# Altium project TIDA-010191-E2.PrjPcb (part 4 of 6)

## Sheet TIDA-010191-E2_LMX2615_LO.SchDoc: LMK0482x
size 558 x 431 mm; Date: Not shown in title block; ApprovedBy: Not shown in title block; CheckedBy: Not shown in title block; Author: Not shown in title block; CompanyName: Not shown in title block; DrawnBy: Avinash N; Engineer: Not shown in title block; Organization: Not shown in title block; Address1: Not shown in title block; Address2: Not shown in title block; Address3: Not shown in title block; Address4: Not shown in title block; DocumentNumber: 5; Revision: Use project parameter SCH_Rev; SheetNumber: 5; SheetTotal: 9; PageSetup: Record=PageOptions¦CenterHorizontal=True¦CenterVertical=True¦PrintScale=1.00¦XCorrection=1.00¦YCorrection=1.00¦PrintKind=0¦BorderSize=5000000¦LeftOffset=0¦BottomOffset=0¦Orientation=2¦PaperLength=1000¦PaperWidth=1000¦Scale=100¦PaperSource=15¦PrintQuality=600¦MediaType=1¦DitherType=10¦PaperKind=Letter¦PrintScaleMode=1
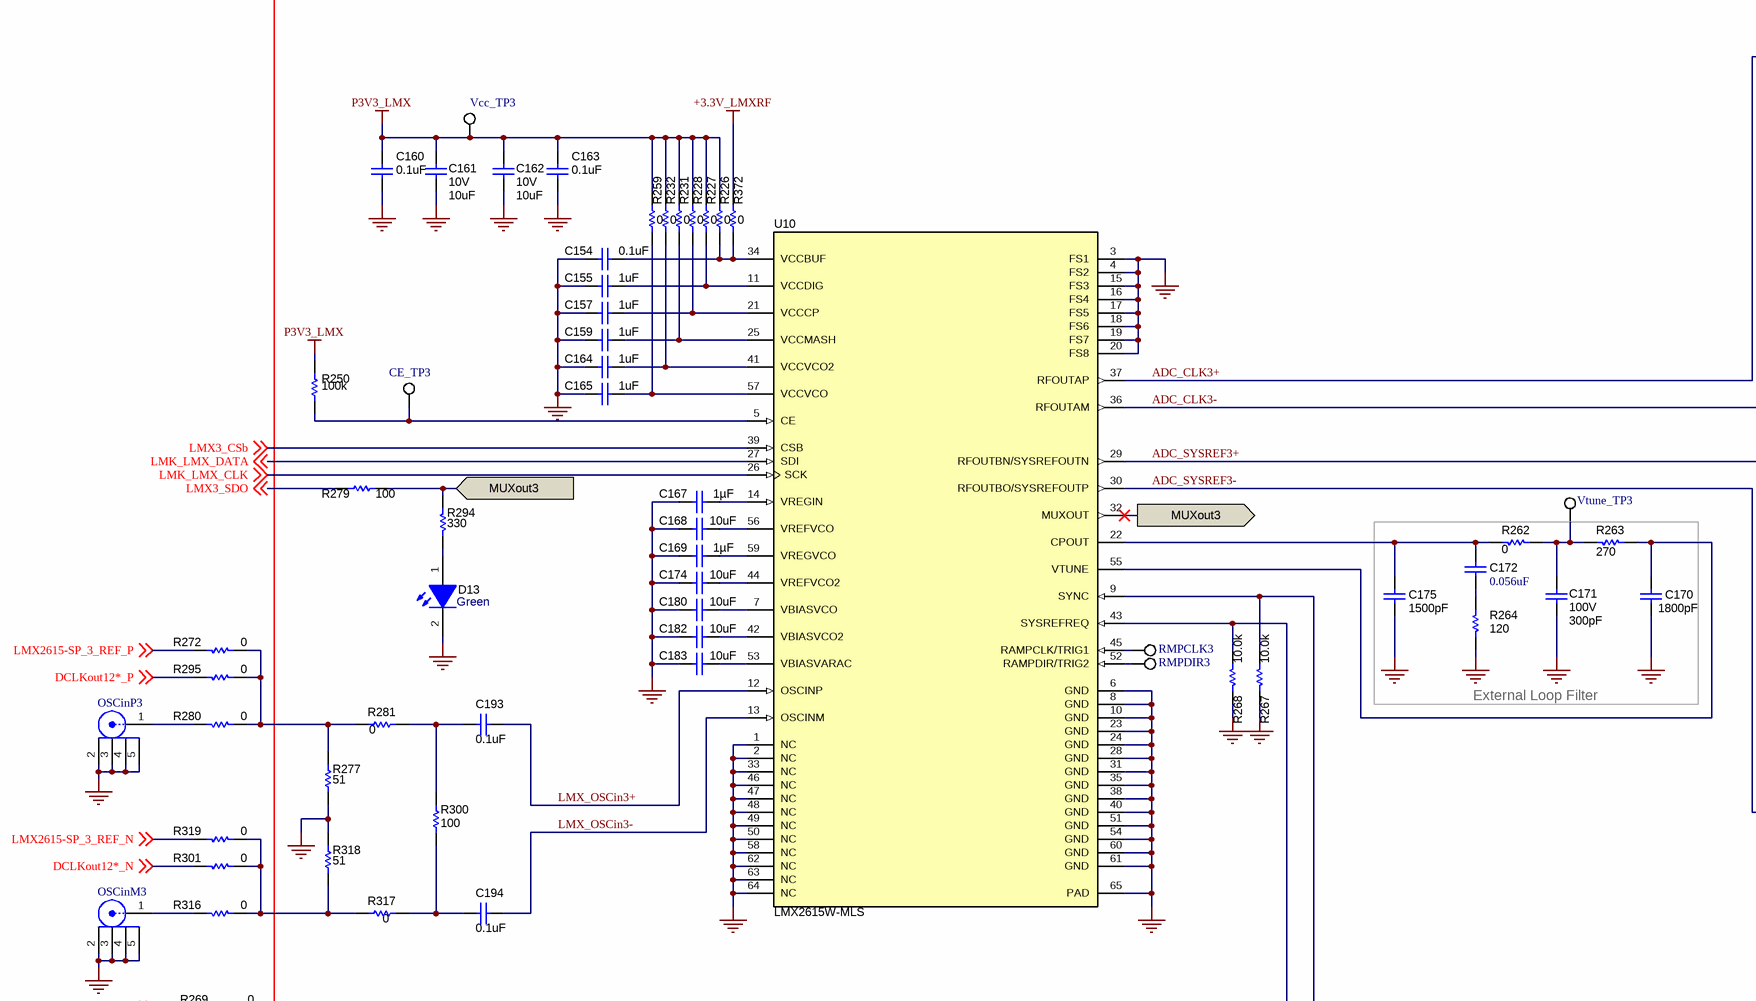
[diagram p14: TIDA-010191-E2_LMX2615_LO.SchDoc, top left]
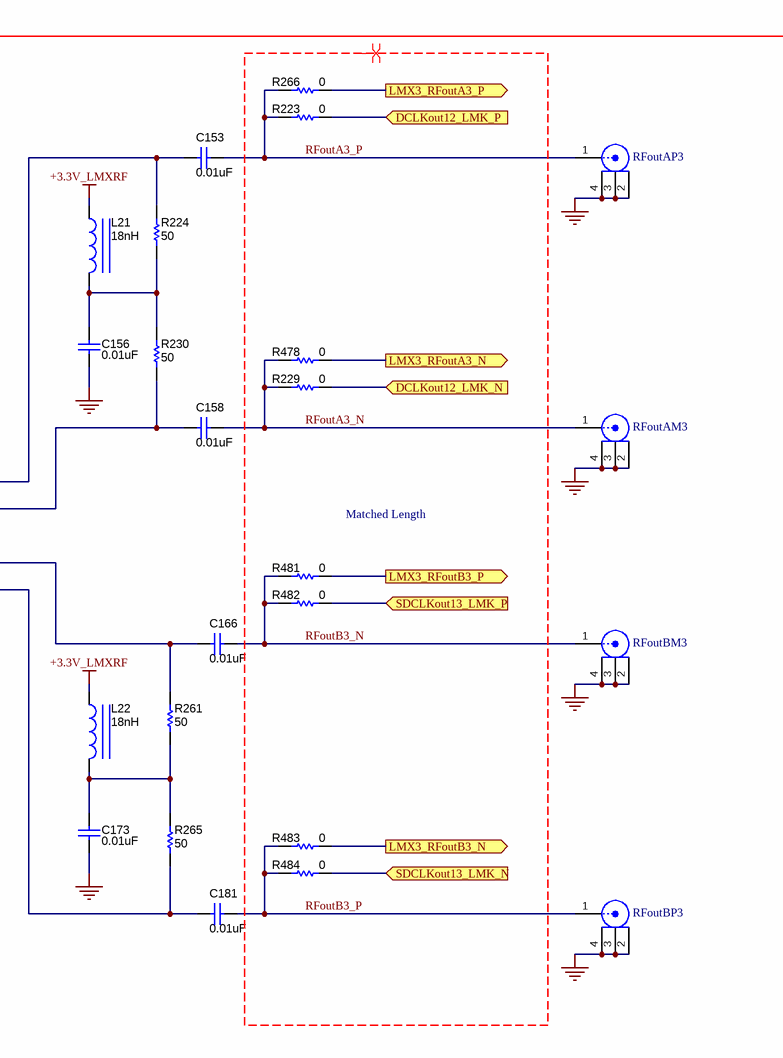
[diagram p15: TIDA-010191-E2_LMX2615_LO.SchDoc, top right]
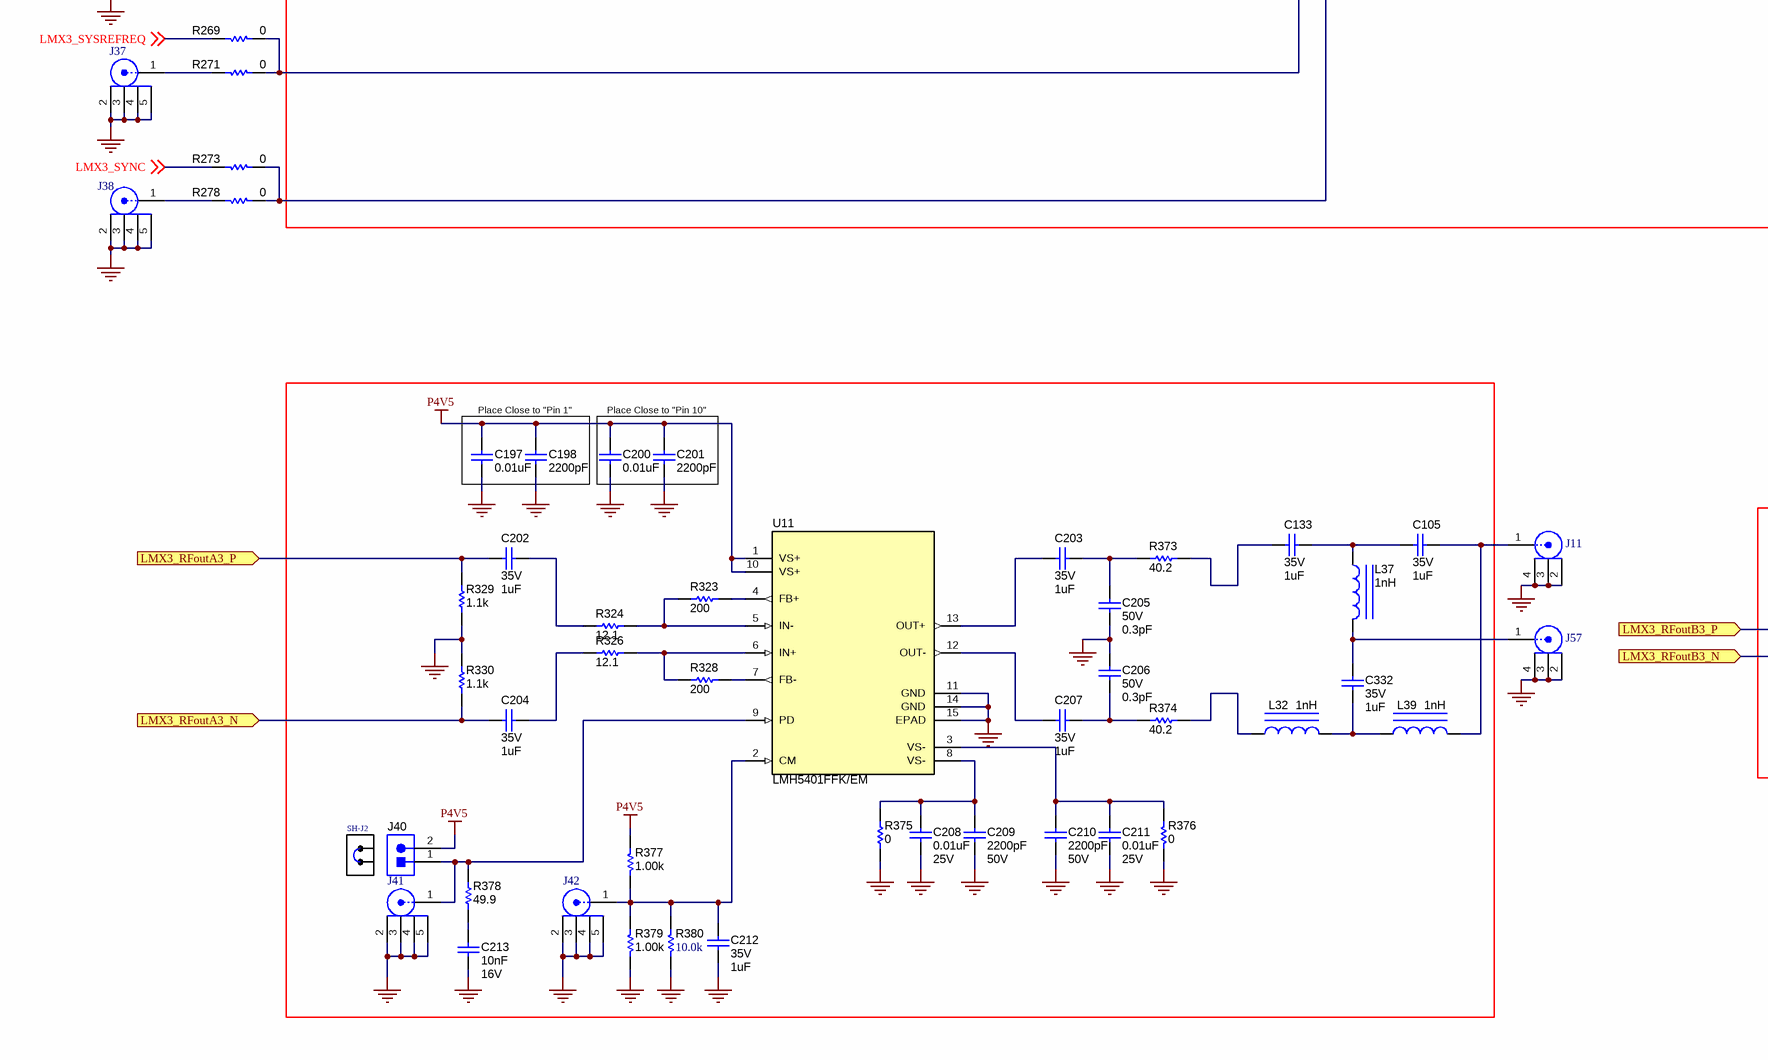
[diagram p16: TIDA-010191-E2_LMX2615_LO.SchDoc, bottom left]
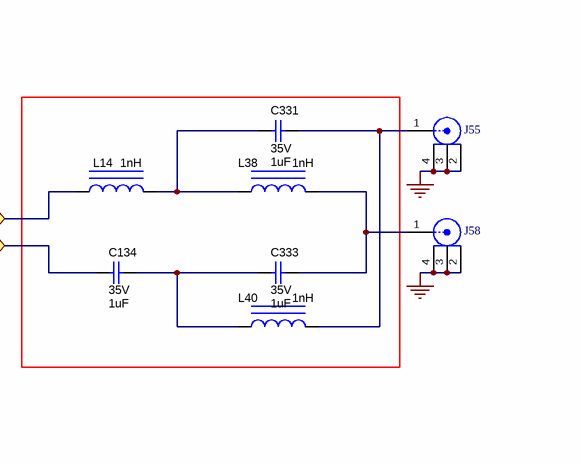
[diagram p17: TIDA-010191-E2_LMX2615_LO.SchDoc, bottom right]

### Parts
C105  VDC_V: 35V  ValueDisplayed: 1uF  [0402]  (hidden comment: GRM155R6YA105KE11D)
C133  VDC_V: 35V  ValueDisplayed: 1uF  [0402]  (hidden comment: GRM155R6YA105KE11D)
C134  VDC_V: 35V  ValueDisplayed: 1uF  [0402]  (hidden comment: GRM155R6YA105KE11D)
C153  ValueDisplayed: 0.01uF  [0402_065]  (hidden comment: Capacitor)
C154  ValueDisplayed: 0.1uF  [0603L]  (hidden comment: Capacitor)
C155  ValueDisplayed: 1uF  [0603]  (hidden comment: Capacitor)
C156  ValueDisplayed: 0.01uF  [0402_065]  (hidden comment: Capacitor)
C157  ValueDisplayed: 1uF  [0603L]  (hidden comment: Capacitor)
C158  ValueDisplayed: 0.01uF  [0402_065]  (hidden comment: Capacitor)
C159  ValueDisplayed: 1uF  [0603L]  (hidden comment: Capacitor)
C160  ValueDisplayed: 0.1uF  [0603]  (hidden comment: Capacitor)
C161  VDC_V: 10V  ValueDisplayed: 10uF  [0805_HV]  (hidden comment: CMP-0007732-2)
C162  VDC_V: 10V  ValueDisplayed: 10uF  [0805_HV]  (hidden comment: CMP-0007732-2)
C163  ValueDisplayed: 0.1uF  [0603]  (hidden comment: Capacitor)
C164  ValueDisplayed: 1uF  [0603]  (hidden comment: Capacitor)
C165  ValueDisplayed: 1uF  [0603]  (hidden comment: Capacitor)
C166  ValueDisplayed: 0.01uF  [0402_065]  (hidden comment: Capacitor)
C167  Cap_F: 1µF  [0603]  (hidden comment: CMP-0007037-4)
C168  ValueDisplayed: 10uF  [0603]  (hidden comment: CMP-0007003-5)
C169  Cap_F: 1µF  [0603]  (hidden comment: CMP-0007037-4)
C170  ValueDisplayed: 1800pF  [0603]  (hidden comment: Capacitor)
C171  VDC_V: 100V  ValueDisplayed: 300pF  [0603]  (hidden comment: CMP-0007262-4)
C172  ValueDisplayed: 0.056uF  [0603]  (hidden comment: Capacitor)
C173  ValueDisplayed: 0.01uF  [0402_065]  (hidden comment: Capacitor)
C174  ValueDisplayed: 10uF  [0603]  (hidden comment: CMP-0007003-5)
C175  ValueDisplayed: 1500pF  [0603]  (hidden comment: Capacitor)
C180  ValueDisplayed: 10uF  [0603]  (hidden comment: CMP-0007003-5)
C181  ValueDisplayed: 0.01uF  [0402_065]  (hidden comment: Capacitor)
C182  ValueDisplayed: 10uF  [0603]  (hidden comment: CMP-0007003-5)
C183  ValueDisplayed: 10uF  [0603]  (hidden comment: CMP-0007003-5)
C193  ValueDisplayed: 0.1uF  [0603L]  (hidden comment: Capacitor)
C194  ValueDisplayed: 0.1uF  [0603L]  (hidden comment: Capacitor)
C197  ValueDisplayed: 0.01uF  [0306]  (hidden comment: Capacitor)
C198  ValueDisplayed: 2200pF  [0306]  (hidden comment: Capacitor)
C200  ValueDisplayed: 0.01uF  [0306]  (hidden comment: Capacitor)
C201  ValueDisplayed: 2200pF  [0306]  (hidden comment: Capacitor)
C202  VDC_V: 35V  ValueDisplayed: 1uF  [0402]  (hidden comment: GRM155R6YA105KE11D)
C203  VDC_V: 35V  ValueDisplayed: 1uF  [0402]  (hidden comment: GRM155R6YA105KE11D)
C204  VDC_V: 35V  ValueDisplayed: 1uF  [0402]  (hidden comment: GRM155R6YA105KE11D)
C205  VDC_V: 50V  ValueDisplayed: 0.3pF  [0402]  (hidden comment: 500R07S0R3BV4T)
C206  VDC_V: 50V  ValueDisplayed: 0.3pF  [0402]  (hidden comment: 500R07S0R3BV4T)
C207  VDC_V: 35V  ValueDisplayed: 1uF  [0402]  (hidden comment: GRM155R6YA105KE11D)
C208  ValueDisplayed: 0.01uF  VDC_V: 25V  [0306]  (hidden comment: CMP-0009490-2)
C209  ValueDisplayed: 2200pF  VDC_V: 50V  [0306]  (hidden comment: CMP-0009493-2)
C210  ValueDisplayed: 2200pF  VDC_V: 50V  [0306]  (hidden comment: CMP-0009493-2)
C211  ValueDisplayed: 0.01uF  VDC_V: 25V  [0306]  (hidden comment: CMP-0009490-2)
C212  VDC_V: 35V  ValueDisplayed: 1uF  [0402]  (hidden comment: GRM155R6YA105KE11D)
C213  Cap_F: 10nF  VDC_V: 16V  [0603]  (hidden comment: GRM188R71C103KA01D)
C331  VDC_V: 35V  ValueDisplayed: 1uF  [0402]  (hidden comment: GRM155R6YA105KE11D)
C332  VDC_V: 35V  ValueDisplayed: 1uF  [0402]  (hidden comment: GRM155R6YA105KE11D)
C333  VDC_V: 35V  ValueDisplayed: 1uF  [0402]  (hidden comment: GRM155R6YA105KE11D)
CE_TP3  5007  [Keystone5007]  (value not drawn)
D13  value Green  [LTST-C191_Green]  (hidden comment: CMP-0002891-3)
J11  142-0771-831  [Johnson_142-0771-831]  (value not drawn)
J37  142-0701-201  [Johnson_142-0701-20x]  (value not drawn)
J38  142-0701-201  [Johnson_142-0701-20x]  (value not drawn)
J40  HTSW-102-07-G-S  [Samtec_HTSW-102-07-G-S]  (value not drawn)
J41  SMA_Contact1_GND2345  [Johnson_142-0701-20x]  (value not drawn)
J42  SMA_Contact1_GND2345  [Johnson_142-0701-20x]  (value not drawn)
J55  142-0771-831  [Johnson_142-0771-831]  (value not drawn)
J57  142-0771-831  [Johnson_142-0771-831]  (value not drawn)
J58  142-0771-831  [Johnson_142-0771-831]  (value not drawn)
L14  ValueDisplayed: 1nH  [IND_LQG15H]  (hidden comment: Inductor_Iron)
L21  ValueDisplayed: 18nH  [IND_LQG15H]  (hidden comment: CMP-0058614-1)
L22  ValueDisplayed: 18nH  [IND_LQG15H]  (hidden comment: CMP-0058614-1)
L32  ValueDisplayed: 1nH  [IND_LQG15H]  (hidden comment: Inductor_Iron)
L37  ValueDisplayed: 1nH  [IND_LQG15H]  (hidden comment: Inductor_Iron)
L38  ValueDisplayed: 1nH  [IND_LQG15H]  (hidden comment: Inductor_Iron)
L39  ValueDisplayed: 1nH  [IND_LQG15H]  (hidden comment: Inductor_Iron)
L40  ValueDisplayed: 1nH  [IND_LQG15H]  (hidden comment: Inductor_Iron)
OSCinM3  CMP-0055819-1  [Johnson_142-0701-20x]  (value not drawn)
OSCinP3  CMP-0055819-1  [Johnson_142-0701-20x]  (value not drawn)
R223  ValueDisplayed: 0  [0402]  (hidden comment: Resistor)
R224  ValueDisplayed: 50  [0402]  (hidden comment: CMP-0026791-1)
R226  value 0  [0603]  (hidden comment: Resistor)
R227  value 0  [0603]  (hidden comment: Resistor)
R228  value 0  [0603L]  (hidden comment: Resistor)
R229  ValueDisplayed: 0  [0402]  (hidden comment: Resistor)
R230  ValueDisplayed: 50  [0402]  (hidden comment: CMP-0026791-1)
R231  value 0  [0603L]  (hidden comment: Resistor)
R232  value 0  [0603]  (hidden comment: Resistor)
R250  ValueDisplayed: 100k  [0603]  (hidden comment: Resistor)
R259  value 0  [0603]  (hidden comment: Resistor)
R261  ValueDisplayed: 50  [0402]  (hidden comment: CMP-0026791-1)
R262  ValueDisplayed: 0  [0603]  (hidden comment: Resistor)
R263  ValueDisplayed: 270  [0603]  (hidden comment: Resistor)
R264  ValueDisplayed: 120  [0603]  (hidden comment: Resistor)
R265  ValueDisplayed: 50  [0402]  (hidden comment: CMP-0026791-1)
R266  ValueDisplayed: 0  [0402]  (hidden comment: Resistor)
R267  ValueDisplayed: 10.0k  [0402]  (hidden comment: Resistor)
R268  ValueDisplayed: 10.0k  [0402]  (hidden comment: Resistor)
R269  ValueDisplayed: 0  [0402]  (hidden comment: CMP-0026822-3)
R271  ValueDisplayed: 0  [0402]  (hidden comment: CMP-0026822-3)
R272  ValueDisplayed: 0  [0402]  (hidden comment: CMP-0026822-3)
R273  ValueDisplayed: 0  [0402]  (hidden comment: CMP-0026822-3)
R277  ValueDisplayed: 51  [0603]  (hidden comment: Resistor)
R278  ValueDisplayed: 0  [0402]  (hidden comment: Resistor)
R279  ValueDisplayed: 100  [0603]  (hidden comment: CMP-0021991-4)
R280  ValueDisplayed: 0  [0402]  (hidden comment: CMP-0026822-3)
R281  ValueDisplayed: 0  [0603]  (hidden comment: Resistor)
R294  value 330  [0603]  (hidden comment: Resistor)
R295  ValueDisplayed: 0  [0402]  (hidden comment: CMP-0026822-3)
R300  ValueDisplayed: 100  [0603]  (hidden comment: CMP-0021991-4)
R301  ValueDisplayed: 0  [0402]  (hidden comment: CMP-0026822-3)
R316  ValueDisplayed: 0  [0402]  (hidden comment: CMP-0026822-3)
R317  ValueDisplayed: 0  [0603]  (hidden comment: Resistor)
R318  ValueDisplayed: 51  [0603]  (hidden comment: Resistor)
R319  ValueDisplayed: 0  [0402]  (hidden comment: CMP-0026822-3)
R323  ValueDisplayed: 200  [0402]  (hidden comment: CRCW0402200RFKED)
R324  ValueDisplayed: 12.1  [0402]  (hidden comment: CRCW040212R1FKED)
R326  ValueDisplayed: 12.1  [0402]  (hidden comment: CRCW040212R1FKED)
R328  ValueDisplayed: 200  [0402]  (hidden comment: CRCW0402200RFKED)
R329  ValueDisplayed: 1.1k  [0402]  (hidden comment: CRCW04021K10JNED)
R330  ValueDisplayed: 1.1k  [0402]  (hidden comment: CRCW04021K10JNED)
R372  value 0  [0603]  (hidden comment: Resistor)
R373  ValueDisplayed: 40.2  [0402]  (hidden comment: CRCW040240R2FKED)
R374  ValueDisplayed: 40.2  [0402]  (hidden comment: CRCW040240R2FKED)
R375  ValueDisplayed: 0  [0402]  (hidden comment: CRCW04020000Z0ED)
R376  ValueDisplayed: 0  [0402]  (hidden comment: CRCW04020000Z0ED)
R377  ValueDisplayed: 1.00k  [0603]  (hidden comment: CRCW06031K00FKEA)
R378  ValueDisplayed: 49.9  [0603]  (hidden comment: CRCW060349R9FKEA)
R379  ValueDisplayed: 1.00k  [0603]  (hidden comment: CRCW06031K00FKEA)
R380  ValueDisplayed: 10.0k  [0402]  (hidden comment: ERJ-2RKF1002X)
R478  ValueDisplayed: 0  [0402]  (hidden comment: Resistor)
R481  ValueDisplayed: 0  [0402]  (hidden comment: Resistor)
R482  ValueDisplayed: 0  [0402]  (hidden comment: Resistor)
R483  ValueDisplayed: 0  [0402]  (hidden comment: Resistor)
R484  ValueDisplayed: 0  [0402]  (hidden comment: Resistor)
RFoutAM3  142-0771-831  [Johnson_142-0771-831]  (value not drawn)
RFoutAP3  142-0771-831  [Johnson_142-0771-831]  (value not drawn)
RFoutBM3  142-0771-831  [Johnson_142-0771-831]  (value not drawn)
RFoutBP3  142-0771-831  [Johnson_142-0771-831]  (value not drawn)
RMPCLK3  5007  [Keystone5007]  (value not drawn)
RMPDIR3  5007  [Keystone5007]  (value not drawn)
SH-J2  SPC02SYAN  [SPC02SYAN]  (value not drawn)
U10  LMX2615W-MLS  [HBD0064A_Custom_A]
U11  LMH5401FFK/EM  [FFK0014A]
Vcc_TP3  5007  [Keystone5007]  (value not drawn)
Vtune_TP3  5007  [Keystone5007]  (value not drawn)

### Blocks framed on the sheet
Matched Length: C153-C175 C180-C183 C193 C194 CE_TP3 D13 L21 L22 R223 R224 R226-R232 R250 R259 R261-R268 R277 R279 R281 R294 R300 R317 R318 R372 R478 R481-R484 RFoutAM3 RFoutAP3 RFoutBM3 RFoutBP3 RMPCLK3 RMPDIR3 U10 Vcc_TP3 Vtune_TP3
Place Close to "Pin 1": C197 C198
Place Close to "Pin 10": C200 C201

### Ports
DCLKout12_LMK_N (in), DCLKout12_LMK_P (in), LMX3_RFoutA3_N (in), LMX3_RFoutA3_N (out), LMX3_RFoutA3_P (in), LMX3_RFoutA3_P (out), LMX3_RFoutB3_N (in), LMX3_RFoutB3_N (out), LMX3_RFoutB3_P (in), LMX3_RFoutB3_P (out), MUXout3 (in), MUXout3 (out), SDCLKout13_LMK_N (in), SDCLKout13_LMK_P (in)

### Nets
+3.3V_LMXRF: L21.1 L22.1 R372.1
GND: C154.1 C155.1 C156.1 C157.1 C159.2 C160.1 C161.1 C162.1 C163.1 C164.1 C165.1 C167.1 C168.2 C169.1 C170.1 C171.2 C173.1 C174.2 C175.2 C180.2 C182.2 C183.2 C197.2 C198.2 C200.1 C201.2 C205.2 C206.2 C208.1 C209.2 C210.2 C211.1 C212.2 C213.2 D13.2(K) J11.2 J11.3 J11.4 J37.2 J37.3 J37.4 J37.5 J38.2 J38.3 J38.4 J38.5 J41.2 J41.3 J41.4 J41.5 J42.2 J42.3 J42.4 J42.5 J55.2 J55.3 J55.4 J57.2 J57.3 J57.4 J58.2 J58.3 J58.4 OSCinM3.2 OSCinM3.3 OSCinM3.4 OSCinM3.5 OSCinP3.2 OSCinP3.3 OSCinP3.4 OSCinP3.5 R264.2 R267.2 R268.2 R277.2 R318.1 R329.1 R330.1 R375.1 R376.1 R379.1 R380.1 RFoutAM3.2 RFoutAM3.3 RFoutAM3.4 RFoutAP3.2 RFoutAP3.3 RFoutAP3.4 RFoutBM3.2 RFoutBM3.3 RFoutBM3.4 RFoutBP3.2 RFoutBP3.3 RFoutBP3.4 U10.1(NC) U10.2(NC) U10.3(FS1) U10.4(FS2) U10.6(GND) U10.8(GND) U10.10(GND) U10.15(FS3) U10.16(FS4) U10.17(FS5) U10.18(FS6) U10.19(FS7) U10.20(FS8) U10.23(GND) U10.24(GND) U10.28(GND) U10.31(GND) U10.33(NC) U10.35(GND) U10.38(GND) U10.40(GND) U10.46(NC) U10.47(NC) U10.48(NC) U10.49(NC) U10.50(NC) U10.51(GND) U10.54(GND) U10.58(NC) U10.60(GND) U10.61(GND) U10.62(NC) U10.63(NC) U10.64(NC) U10.65(PAD) U11.11(GND) U11.14(GND) U11.15(EPAD)
P3V3_LMX: C160.2 C161.2 C162.2 C163.2 R226.1 R227.1 R228.1 R231.1 R232.2 R250.1 R259.2 Vcc_TP3.1
P4V5: C197.1 C198.1 C200.2 C201.1 J40.2 R377.1 U11.1(VS+) U11.10(VS+)
ADC_CLK3+: C153.2 R224.1 U10.37(RFOUTAP)
ADC_CLK3-: C158.2 R230.2 U10.36(RFOUTAM)
ADC_SYSREF3+: C166.2 R261.1 U10.29(RFOUTBN/SYSREFOUTN)
ADC_SYSREF3-: C181.2 R265.2 U10.30(RFOUTBO/SYSREFOUTP)
DCLKout12*_N: R301.2 ; off-sheet DCLKout12*_N
DCLKout12*_P: R295.2 ; off-sheet DCLKout12*_P
DCLKout12_LMK_N: R229.2 ; port DCLKout12_LMK_N
DCLKout12_LMK_P: R223.2 ; port DCLKout12_LMK_P
LMK_LMX_CLK: U10.26(SCK) ; off-sheet LMK_LMX_CLK
LMK_LMX_DATA: U10.27(SDI) ; off-sheet LMK_LMX_DATA
LMX3_CSb: U10.39(CSB) ; off-sheet LMX3_CSb
LMX3_RFoutA3_N: C204.2 R330.2 R478.2 ; port LMX3_RFoutA3_N
LMX3_RFoutA3_P: C202.2 R266.2 R329.2 ; port LMX3_RFoutA3_P
LMX3_RFoutB3_N: C134.2 R483.2 ; port LMX3_RFoutB3_N
LMX3_RFoutB3_P: L14.1 R481.2 ; port LMX3_RFoutB3_P
LMX3_SDO: R279.2 ; off-sheet LMX3_SDO
LMX3_SYNC: R273.2 ; off-sheet LMX3_SYNC
LMX3_SYSREFREQ: R269.2 ; off-sheet LMX3_SYSREFREQ
LMX2615-SP_3_REF_N: R319.2 ; off-sheet LMX2615-SP_3_REF_N
LMX2615-SP_3_REF_P: R272.2 ; off-sheet LMX2615-SP_3_REF_P
LMX_OSCin3+: C193.2 U10.12(OSCINP)
LMX_OSCin3-: C194.2 U10.13(OSCINM)
MUXout3: R279.1 R294.2 U10.32(MUXOUT) ; port MUXout3
RFoutA3_N: C158.1 R229.1 R478.1 RFoutAM3.1
RFoutA3_P: C153.1 R223.1 R266.1 RFoutAP3.1
RFoutB3_N: C166.1 R481.1 R482.1 RFoutBM3.1
RFoutB3_P: C181.1 R483.1 R484.1 RFoutBP3.1
SDCLKout13_LMK_N: R484.2 ; port SDCLKout13_LMK_N
SDCLKout13_LMK_P: R482.2 ; port SDCLKout13_LMK_P
NetC105_1: C105.1 J11.1 L39.2
NetC105_2: C105.2 C133.1 L37.1
NetC133_2: C133.2 R373.2
NetC134_1: C134.1 C333.2 L40.1
NetC154_2: C154.2 R226.2 R372.2 U10.34(VCCBUF)
NetC155_2: C155.2 R227.2 U10.11(VCCDIG)
NetC156_2: C156.2 L21.2 R224.2 R230.1
NetC157_2: C157.2 R228.2 U10.21(VCCCP)
NetC159_1: C159.1 R231.2 U10.25(VCCMASH)
NetC164_2: C164.2 R232.1 U10.41(VCCVCO2)
NetC165_2: C165.2 R259.1 U10.57(VCCVCO)
NetC167_2: C167.2 U10.14(VREGIN)
NetC168_1: C168.1 U10.56(VREFVCO)
NetC169_2: C169.2 U10.59(VREGVCO)
NetC170_2: C170.2 R263.1 U10.55(VTUNE)
NetC171_1: C171.1 R262.2 R263.2 Vtune_TP3.1
NetC172_1: C172.1 C175.1 R262.1 U10.22(CPOUT)
NetC172_2: C172.2 R264.1
NetC173_2: C173.2 L22.2 R261.2 R265.1
NetC174_1: C174.1 U10.44(VREFVCO2)
NetC180_1: C180.1 U10.7(VBIASVCO)
NetC182_1: C182.1 U10.42(VBIASVCO2)
NetC183_1: C183.1 U10.53(VBIASVARAC)
NetC193_1: C193.1 R281.2 R300.2
NetC194_1: C194.1 R300.1 R317.1
NetC202_1: C202.1 R324.1
NetC203_1: C203.1 C205.1 R373.1
NetC203_2: C203.2 U11.13(OUT+)
NetC204_1: C204.1 R326.1
NetC206_1: C206.1 C207.1 R374.1
NetC207_2: C207.2 U11.12(OUT-)
NetC208_2: C208.2 C209.1 R375.2 U11.8(VS-)
NetC210_1: C210.1 C211.2 R376.2 U11.3(VS-)
NetC212_1: C212.1 J42.1 R377.2 R379.2 R380.2 U11.2(CM)
NetC213_1: C213.1 R378.1
NetC331_1: C331.1 J55.1 L40.2
NetC331_2: C331.2 L14.2 L38.1
NetC332_1: C332.1 J57.1 L37.2
NetC332_2: C332.2 L32.2 L39.1
NetC333_1: C333.1 J58.1 L38.2
NetCE_TP3_1: CE_TP3.1 R250.2 U10.5(CE)
NetD13_1: D13.1(A) R294.1
NetJ37_1: J37.1 R271.2
NetJ38_1: J38.1 R278.2
NetJ40_1: J40.1 J41.1 R378.2 U11.9(PD)
NetL32_1: L32.1 R374.2
NetOSCinM3_1: OSCinM3.1 R316.2
NetOSCinP3_1: OSCinP3.1 R280.2
NetR267_1: R267.1 R273.1 R278.1 U10.9(SYNC)
NetR268_1: R268.1 R269.1 R271.1 U10.43(SYSREFREQ)
NetR272_1: R272.1 R277.1 R280.1 R281.1 R295.1
NetR301_1: R301.1 R316.1 R317.2 R318.2 R319.1
NetR323_1: R323.1 R324.2 U11.5(IN-)
NetR323_2: R323.2 U11.4(FB+)
NetR326_2: R326.2 R328.1 U11.6(IN+)
NetR328_2: R328.2 U11.7(FB-)
NetRMPCLK3_1: RMPCLK3.1 U10.45(RAMPCLK/TRIG1)
NetRMPDIR3_1: RMPDIR3.1 U10.52(RAMPDIR/TRIG2)

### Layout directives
differential pair; differential pair class 100ohm: RFoutA3_N, RFoutA3_P, RFoutB3_N, RFoutB3_P

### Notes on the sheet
- (near R264) External Loop Filter

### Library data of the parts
C105 C133 C134 C202-C204 C207 C212 C331-C333 = CMP-0006619-2: CAP, CERM, 1 uF, 35 V, +/- 10%, X5R, 0402; Manufacturer: MuRata; TaMin_C: -55°C; Polarized: N; SizeAreaWB_mm2: 3; Value1: Unknown; U/M: EA; Value: 1uF; TaMax_C: 85°C; SizeZ_mm: 0.6; SizeX_mm: 1; SizeY_mm: 0.5; Cap_F: 1µF; AEC Category: Q200
C153 C156 C158 C166 C173 C181 = CMP-0006210-2: CAP, CERM, 0.01 uF, 16 V, +/- 10%, X7R, 0402; PartNumber: 520L103KT16T; Manufacturer: AT Ceramics; Polarized: N; Value: 0.01uF; U/M: EA; Cap_F: 10nF; Value1: Unknown; VDC_V: 16V; TaMin_C: -55°C; TaMax_C: 125°C; Cap_Case: 0402; AEC Category: Q200; SizeArea_mm2: 0.5; SizeAreaWB_mm2: 3; SizeX_mm: 1; SizeZ_mm: 0.65
C154 C193 C194 = CMP-0006808-4: CAP, CERM, 0.1 uF, 16 V, +/- 5%, X7R, 0603; Manufacturer: AVX; PartNumber: 0603YC104JAT2A; Cap_Case: 0603; ESR_ohm: 0.039; Polarized: N; TaMax_C: 125°C; TaMin_C: -55°C; VDC_V: 16V; Cap_F: 100nF; Value: 0.1uF; Value1: 0.039 ohm; U/M: EA; AEC Category: Q200; SizeArea_mm2: 1.28; SizeAreaWB_mm2: 4.68; SizeX_mm: 1.6; SizeY_mm: 0.8; SizeZ_mm: 1
C155 C164 C165 = CMP-0007037-4: CAP, CERM, 1 uF, 16 V, +/- 10%, X7R, 0603; Manufacturer: TDK; PartNumber: C1608X7R1C105K080AC; ESR_ohm: 5.7m; Polarized: N; TaMax_C: 125°C; TaMin_C: -55°C; VDC_V: 16V; Cap_F: 1µF; Value: 1uF; Value1: 0.0057 ohm; U/M: EA; SizeArea_mm2: 1.28; SizeAreaWB_mm2: 4.68; SizeX_mm: 1.6; SizeY_mm: 0.8; SizeZ_mm: 1; AEC Category: Q200
C157 C159 = CMP-0007037-4: CAP, CERM, 1 uF, 16 V, +/- 10%, X7R, 0603; Manufacturer: TDK; PartNumber: C1608X7R1C105K080AC; Cap_Case: 0603; ESR_ohm: 5.7m; Polarized: N; TaMax_C: 125°C; TaMin_C: -55°C; VDC_V: 16V; Cap_F: 1µF; Value: 1uF; Value1: 0.0057 ohm; U/M: EA; SizeArea_mm2: 1.28; SizeAreaWB_mm2: 4.68; SizeX_mm: 1.6; SizeY_mm: 0.8; SizeZ_mm: 1; AEC Category: Q200
C160 C163 = CMP-0006808-4: CAP, CERM, 0.1 uF, 16 V, +/- 5%, X7R, 0603; Manufacturer: AVX; PartNumber: 0603YC104JAT2A; ESR_ohm: 0.039; Polarized: N; TaMax_C: 125°C; TaMin_C: -55°C; VDC_V: 16V; Cap_F: 100nF; Value: 0.1uF; Value1: 0.039 ohm; U/M: EA; AEC Category: Q200; SizeArea_mm2: 1.28; SizeAreaWB_mm2: 4.68; SizeX_mm: 1.6; SizeY_mm: 0.8; SizeZ_mm: 1
C161 C162 = CMP-0007732-2: CAP, CERM, 10 uF, 10 V, +/- 10%, X5R, 0805; Manufacturer: Kemet; PartNumber: C0805C106K8PACTU; Cap_Case: 0805; ESR_ohm: 3m; IRMS_A: 11.43A; Polarized: N; TaMax_C: 85°C; TaMin_C: -55°C; Cap_F: 10µF; Value: 10uF; U/M: EA; Value1: 0.003 ohm; SizeAreaWB_mm2: 6.75; SizeZ_mm: 1.45; SizeX_mm: 2; SizeY_mm: 1.25; SizeArea_mm2: 2.5; AEC Category: Q200
C167 C169 = CMP-0007037-4: CAP, CERM, 1 uF, 16 V, +/- 10%, X7R, 0603; Manufacturer: TDK; PartNumber: C1608X7R1C105K080AC; ESR_ohm: 5.7m; Polarized: N; TaMax_C: 125°C; TaMin_C: -55°C; VDC_V: 16V; Value: 1uF; U/M: EA; Value1: 0.0057 ohm; AEC Category: Q200; SizeAreaWB_mm2: 4.68; SizeZ_mm: 1; SizeX_mm: 1.6; SizeY_mm: 0.8; SizeArea_mm2: 1.28
C168 C174 C180 C182 C183 = CMP-0007003-5: CAP, CERM, 10 uF, 10 V, +/- 20%, X5R, 0603; Manufacturer: TDK; PartNumber: C1608X5R1A106M080AC; ESR_ohm: 7.8m; IRMS_A: 1.85A; Polarized: N; TaMax_C: 85°C; TaMin_C: -55°C; VDC_V: 10V; Cap_F: 10µF; Value: 10uF; U/M: EA; Value1: 0.0078 ohm; AEC Category: Q200; SizeAreaWB_mm2: 4.68; SizeZ_mm: 1; SizeX_mm: 1.6; SizeY_mm: 0.8; SizeArea_mm2: 1.28
C170 = CMP-0007192-4: CAP, CERM, 1800 pF, 50 V, +/- 5%, C0G/NP0, 0603; Manufacturer: MuRata; PartNumber: GRM1885C1H182JA01D; Polarized: N; TaMax_C: 125°C; TaMin_C: -55°C; VDC_V: 50V; Cap_F: 1.8nF; Value: 1800pF; Value1: Unknown; U/M: EA; SizeArea_mm2: 1.28; SizeAreaWB_mm2: 4.68; SizeX_mm: 1.6; SizeY_mm: 0.8; SizeZ_mm: 1; AEC Category: Q200
C171 = CMP-0007262-4: CAP, CERM, 300 pF, 100 V, +/- 5%, C0G/NP0, 0603; Manufacturer: MuRata; PartNumber: GRM1885C2A301JA01D; Polarized: N; TaMax_C: 125°C; TaMin_C: -55°C; Value: 300pF; Value1: Unknown; U/M: EA; SizeAreaWB_mm2: 4.68; SizeZ_mm: 1; SizeX_mm: 1.6; SizeY_mm: 0.8; SizeArea_mm2: 1.28; AEC Category: Q200
C172 = CMP-0007460-5: CAP, CERM, 0.056 uF, 50 V, +/- 10%, X7R, 0603; Manufacturer: MuRata; PartNumber: GRM188R71H563KA93D; Polarized: N; TaMax_C: 125°C; TaMin_C: -55°C; VDC_V: 50V; Cap_F: 56nF; Value1: Unknown; U/M: EA; AEC Category: Q200; SizeArea_mm2: 1.28; SizeAreaWB_mm2: 4.68; SizeX_mm: 1.6; SizeY_mm: 0.8; SizeZ_mm: 1; MFG_Status: TI_Obsolete
C175 = CMP-0064973-4: CAP, CERM, 1500 pF, 50 V,+/- 5%, C0G/NP0, 0603; Manufacturer: MuRata; PartNumber: GRM1885C1H152JA01J; Polarized: N; TaMax_C: 125°C; TaMin_C: -55°C; VDC_V: 50V; Cap_F: 1.5nF; Value: 1500pF; Value1: Unknown; U/M: EA; AEC Category: Q200; SizeArea_mm2: 1.28; SizeAreaWB_mm2: 4.68; SizeX_mm: 1.6; SizeY_mm: 0.8; SizeZ_mm: 1
C197 C200 = CMP-0009490-2: CAP, CERM, 0.01 uF, 25 V, +/- 20%, X7R, 0306; PartNumber: LLL185R71E103MA01L; Manufacturer: MuRata; Polarized: N; Value: 0.01uF; U/M: EA; Cap_F: 10nF; Value1: Unknown; VDC_V: 25V; TaMin_C: -55°C; TaMax_C: 125°C; SizeArea_mm2: 1.28; SizeAreaWB_mm2: 4.68; SizeX_mm: 0.8; SizeY_mm: 1.6; SizeZ_mm: 0.6; AEC Category: Q200
C198 C201 = CMP-0009493-2: CAP, CERM, 2200 pF, 50 V, +/- 20%, X7R, 0306; PartNumber: LLL185R71H222MA01L; Manufacturer: MuRata; Polarized: N; Value: 2200pF; U/M: EA; Cap_F: 2.2nF; Value1: Unknown; VDC_V: 50V; TaMin_C: -55°C; TaMax_C: 125°C; SizeArea_mm2: 1.28; SizeAreaWB_mm2: 4.68; SizeX_mm: 0.8; SizeY_mm: 1.6; SizeZ_mm: 0.6; AEC Category: Q200
C205 C206 = CMP-0006206-2: CAP, CERM, 0.3 pF, 50 V, +/- 30%, C0G/NP0, 0402; Manufacturer: Johanson Technology; TaMin_C: -55°C; Polarized: N; SizeAreaWB_mm2: 3; Value1: Unknown; U/M: EA; Value: 0.3pF; TaMax_C: 125°C; SizeZ_mm: 0.6; SizeX_mm: 1; SizeY_mm: 0.5; AEC Category: Q200
C208 C211 = CMP-0009490-2: CAP, CERM, 0.01 uF, 25 V, +/- 20%, X7R, 0306; PartNumber: LLL185R71E103MA01L; Manufacturer: MuRata; Polarized: N; Value: 0.01uF; U/M: EA; Cap_F: 10nF; Value1: Unknown; TaMin_C: -55°C; TaMax_C: 125°C; SizeArea_mm2: 1.28; SizeAreaWB_mm2: 4.68; SizeX_mm: 0.8; SizeY_mm: 1.6; SizeZ_mm: 0.6; AEC Category: Q200
C209 C210 = CMP-0009493-2: CAP, CERM, 2200 pF, 50 V, +/- 20%, X7R, 0306; PartNumber: LLL185R71H222MA01L; Manufacturer: MuRata; Polarized: N; Value: 2200pF; U/M: EA; Cap_F: 2.2nF; Value1: Unknown; TaMin_C: -55°C; TaMax_C: 125°C; SizeArea_mm2: 1.28; SizeAreaWB_mm2: 4.68; SizeX_mm: 0.8; SizeY_mm: 1.6; SizeZ_mm: 0.6; AEC Category: Q200
C213 = CMP-0007377-4: CAP, CERM, 0.01 uF, 16 V, +/- 10%, X7R, 0603; Manufacturer: MuRata; TaMin_C: -55°C; Polarized: N; SizeAreaWB_mm2: 4.68; Value1: Unknown; U/M: EA; Value: 0.01uF; TaMax_C: 125°C; SizeZ_mm: 1; SizeX_mm: 1.6; SizeArea_mm2: 1.28; AEC Category: Q200; SizeY_mm: 0.8
CE_TP3 RMPCLK3 RMPDIR3 Vcc_TP3 Vtune_TP3 = CMP-0055144-2: Test Point, Compact, White, TH; Manufacturer: Keystone Electronics; CNHeader: FALSE; ContactFinish: Silver; CT: TRUE; Green_Lifecycle: Active; Green_REACh: Passed
D13 = CMP-0002891-3: LED, Green, SMD; Manufacturer: Lite-On; PartNumber: LTST-C191TGKT; Type: InGaN; Vf_V: 3.2V; Io_A: 20mA; Value1: W
J11 J55 J57 J58 RFoutAM3 RFoutAP3 RFoutBM3 RFoutBP3 = CMP-0055844-3: JACK, SMA, 50 Ohm, Gold, Edge Mount; Manufacturer: Cinch Connectivity; Gender: Female; Voltage_V: 170V
J37 J38 = CMP-0055819-1: Connector, SMA, TH; Manufacturer: Cinch Connectivity; CT: TRUE; CNHeader: FALSE; Green_Lifecycle: Not Set; Green_REACh: Incomplete
J40 = CMP-0075483-1: Header, 100mil, 2x1, Gold, TH; Manufacturer: Samtec; Green_REACh: Passed; CT: False; Green_Lifecycle: Active; CNHeader: True
J41 J42 = CMP-0055819-1: Connector, SMA, TH; PartNumber: 142-0701-201; Manufacturer: Cinch Connectivity; CNHeader: FALSE; CT: TRUE; Green_Lifecycle: Not Set; Green_REACh: Incomplete
L14 L32 L37-L40 = CMP-0058615-1: Inductor, Multilayer, Air Core, 1 nH, 0.3 A, 0.07 ohm, SMD; PartNumber: LQG15HS1N0S02D; Manufacturer: MuRata; Value: 1nH; Imax_A: 300mA; Irms: 0.3A @ C rise; Isat: 0.3A @ % inductance drop; DCR_ohm: 0.07; Value2: 0.3A; SizeAreaWB_mm2: 3; SizeArea_mm2: 0.5; SizeX_mm: 1; SizeZ_mm: 0.55; AEC Category: Q200; Green_Lifecycle: Active; Green_REACh: Passed
L21 L22 = CMP-0058614-1: Inductor, Multilayer, Air Core, 18 nH, 0.3 A, 0.36 ohm, SMD; PartNumber: LQG15HS18NJ02D; Manufacturer: MuRata; Value: 18nH; Imax_A: 300mA; Irms: 0.3A @ C rise; Isat: 0.3A @ % inductance drop; DCR_ohm: 0.36; Value2: 0.3A; AEC Category: Q200; Green_Lifecycle: Active; SizeAreaWB_mm2: 3; Green_REACh: Passed; SizeZ_mm: 0.55; SizeX_mm: 1; SizeY_mm: 0.5
OSCinM3 OSCinP3 = CMP-0055819-1: Connector, SMA, TH; PartNumber: 142-0701-201; Manufacturer: Cinch Connectivity; CNHeader: FALSE; Green_Lifecycle: Not Set; Green_REACh: Incomplete; CT: TRUE
R223 R229 R266 R269 R271-R273 R278 R280 R295 R301 R316 R319 R478 R481-R484 = CMP-0026822-3: RES, 0, 5%, 0.063 W, AEC-Q200 Grade 0, 0402; PartNumber: CRCW04020000Z0ED; Manufacturer: Vishay-Dale; Value: 0; Value_Code: 0000; Power_W: 63mW; Value2: 0.063W; VDC_V: 50V; TempCo: 200 ppm/C; SizeArea_mm2: 0.5; SizeX_mm: 1; SizeZ_mm: 0.6; EIA_Code: E24; AEC Category: Q200; AEC Qualified: Y
R224 R230 R261 R265 = CMP-0026791-1: RES, 50, 0.1%, 0.05 W, 0402; PartNumber: FC0402E50R0BST1; Manufacturer: Vishay-Dale; Value: 50; Value_Code: 50R0; Power_W: 50mW; Value2: 0.05W; TempCo: 25 ppm/C; U/M: EA; SizeArea_mm2: 0.5; SizeX_mm: 1; SizeZ_mm: 0.6; AEC Category: Q200; AEC Qualified: N
R226-R228 R231 R232 R259 R372 = CMP-0025697-4: RES, 0, 5%, 0.1 W, AEC-Q200 Grade 0, 0603; Manufacturer: Vishay-Dale; PartNumber: CRCW06030000Z0EA; VDC_V: 75V; Power_W: 100mW; Value_Code: 0000; Value2: 0.1W; EIA_Code: E24; AEC Category: Q200; AEC Qualified: Y; SizeArea_mm2: 1.28; SizeX_mm: 1.6; SizeY_mm: 0.8; SizeZ_mm: 1; TempCo: 200 ppm/C
R250 = CMP-0025698-4: RES, 100 k, 5%, 0.1 W, AEC-Q200 Grade 0, 0603; Manufacturer: Vishay-Dale; PartNumber: CRCW0603100KJNEA; VDC_V: 75V; Power_W: 100mW; Value: 100k; Value2: 0.1W; EIA_Code: E24; TempCo: 200 ppm/C; SizeArea_mm2: 1.28; SizeX_mm: 1.6; SizeY_mm: 0.8; SizeZ_mm: 1; AEC Category: Q200; AEC Qualified: Y; AEC Grade: 0
R262 R281 R317 = CMP-0025697-4: RES, 0, 5%, 0.1 W, AEC-Q200 Grade 0, 0603; Manufacturer: Vishay-Dale; PartNumber: CRCW06030000Z0EA; VDC_V: 75V; Power_W: 100mW; Value: 0; Value_Code: 0000; Value2: 0.1W; EIA_Code: E24; TempCo: 200 ppm/C; SizeArea_mm2: 1.28; SizeX_mm: 1.6; SizeY_mm: 0.8; SizeZ_mm: 1; AEC Category: Q200; AEC Qualified: Y
R263 = CMP-0025904-5: RES, 270, 5%, 0.1 W, 0603; Manufacturer: Yageo; PartNumber: RC0603JR-07270RL; VDC_V: 75V; Power_W: 100mW; Value: 270; Value_Code: 270R; Value2: 0.1W; EIA_Code: E24; TempCo: 100 ppm/C; SizeArea_mm2: 1.28; SizeX_mm: 1.6; SizeY_mm: 0.8; SizeZ_mm: 1; AEC Category: Q200; AEC Qualified: N; SizeAreaWB_mm2: 4.68
R264 = CMP-0025710-4: RES, 120, 5%, 0.1 W, AEC-Q200 Grade 0, 0603; Manufacturer: Vishay-Dale; PartNumber: CRCW0603120RJNEA; VDC_V: 75V; Power_W: 100mW; Value: 120; Value_Code: 120R; Value2: 0.1W; TempCo: 200 ppm/C; EIA_Code: E24; SizeArea_mm2: 1.28; SizeX_mm: 1.6; SizeY_mm: 0.8; SizeZ_mm: 1; AEC Category: Q200; AEC Qualified: Y; AEC Grade: 0
R267 R268 = CMP-0026769-2: RES, 10.0 k, 0.5%, 0.063 W, AEC-Q200 Grade 0, 0402; PartNumber: CRCW040210K0DHEDP; Manufacturer: Vishay-Dale; Value: 10.0k; Res_ohm: 10k; Value_Code: 10k0; Power_W: 63mW; Value2: 0.063W; VDC_V: 50V; TempCo: 50 ppm/C; SizeArea_mm2: 0.5; SizeX_mm: 1; SizeZ_mm: 0.6; EIA_Code: E192; AEC Category: Q200; AEC Qualified: Y; AEC Grade: 0
R277 R318 = CMP-0025825-4: RES, 51, 5%, 0.1 W, AEC-Q200 Grade 0, 0603; PartNumber: CRCW060351R0JNEA; Manufacturer: Vishay-Dale; Value: 51; Value_Code: 51R0; Power_W: 100mW; Value2: 0.1W; VDC_V: 75V; TempCo: 200 ppm/C; EIA_Code: E24; SizeArea_mm2: 1.28; SizeX_mm: 1.6; SizeY_mm: 0.8; SizeZ_mm: 1; AEC Category: Q200; AEC Qualified: Y; AEC Grade: 0
R279 R300 = CMP-0021991-4: RES, 100, 1%, 0.1 W, AEC-Q200 Grade 0, 0603; Manufacturer: Vishay-Dale; PartNumber: CRCW0603100RFKEA; VDC_V: 75V; Power_W: 100mW; Value: 100; Value_Code: 100R; Value2: 0.1W; EIA_Code: E96; TempCo: 100 ppm/C; SizeArea_mm2: 1.28; SizeX_mm: 1.6; SizeY_mm: 0.8; SizeZ_mm: 1; AEC Category: Q200; AEC Qualified: Y; AEC Grade: 0
R294 = CMP-0025912-5: RES, 330, 5%, 0.1 W, 0603; Manufacturer: Yageo; PartNumber: RC0603JR-07330RL; VDC_V: 75V; Power_W: 100mW; Value_Code: 330R; Value2: 0.1W; EIA_Code: E24; AEC Category: Q200; AEC Qualified: N; SizeArea_mm2: 1.28; SizeAreaWB_mm2: 4.68; SizeX_mm: 1.6; SizeY_mm: 0.8; SizeZ_mm: 1; TempCo: 100 ppm/C
R323 R328 = CMP-0026159-2: RES, 200, 1%, 0.063 W, AEC-Q200 Grade 0, 0402; Manufacturer: Vishay-Dale; Power_W: 63mW; TempCo: 100 ppm/C; Value_Code: 200R; Value: 200; EIA_Code: E96; SizeX_mm: 1; SizeY_mm: 0.5; SizeZ_mm: 0.6; Value2: 0.063W; AEC Qualified: Y; VDC_V: 50V; AEC Category: Q200; AEC Grade: 0
R324 R326 = CMP-0025994-3: RES, 12.1, 1%, 0.063 W, AEC-Q200 Grade 0, 0402; Manufacturer: Vishay-Dale; Power_W: 63mW; TempCo: 100 ppm/C; Value_Code: 12R1; Value: 12.1; EIA_Code: E96; SizeX_mm: 1; SizeY_mm: 0.5; SizeZ_mm: 0.6; Value2: 0.063W; AEC Qualified: Y; VDC_V: 50V; AEC Category: Q200; AEC Grade: 0
R329 R330 = CMP-0026853-5: RES, 1.1 k, 5%, 0.063 W, AEC-Q200 Grade 0, 0402; Manufacturer: Vishay-Dale; Power_W: 63mW; TempCo: 200 ppm/C; Value_Code: 1k10; Value: 1.1k; EIA_Code: E24; SizeX_mm: 1; SizeY_mm: 0.5; SizeZ_mm: 0.6; Value2: 0.063W; AEC Qualified: Y; VDC_V: 50V; AEC Category: Q200; AEC Grade: 0
R373 R374 = CMP-0026368-2: RES, 40.2, 1%, 0.063 W, AEC-Q200 Grade 0, 0402; Manufacturer: Vishay-Dale; Power_W: 63mW; TempCo: 100 ppm/C; Value_Code: 40R2; Value: 40.2; EIA_Code: E96; SizeX_mm: 1; SizeY_mm: 0.5; SizeZ_mm: 0.6; Value2: 0.063W; AEC Qualified: Y; VDC_V: 50V; AEC Category: Q200; AEC Grade: 0
R375 R376 = CMP-0026822-3: RES, 0, 5%, 0.063 W, AEC-Q200 Grade 0, 0402; Manufacturer: Vishay-Dale; VDC_V: 50V; Power_W: 63mW; Value: 0; Value_Code: 0000; Value2: 0.063W; EIA_Code: E24; TempCo: 200 ppm/C; SizeArea_mm2: 0.5; SizeX_mm: 1; SizeZ_mm: 0.6; AEC Category: Q200; AEC Qualified: Y
R377 R379 = CMP-0022109-5: RES, 1.00 k, 1%, 0.1 W, AEC-Q200 Grade 0, 0603; Manufacturer: Vishay-Dale; Power_W: 100mW; TempCo: 100 ppm/C; Value_Code: 1k00; Value: 1.00k; EIA_Code: E96; Res_ohm: 1k; SizeX_mm: 1.6; SizeY_mm: 0.8; SizeZ_mm: 1; Value2: 0.1W; SizeArea_mm2: 1.28; AEC Qualified: Y; VDC_V: 75V; AEC Category: Q200; AEC Grade: 0
R378 = CMP-0022448-4: RES, 49.9, 1%, 0.1 W, AEC-Q200 Grade 0, 0603; Manufacturer: Vishay-Dale; Power_W: 100mW; TempCo: 100 ppm/C; Value_Code: 49R9; Value: 49.9; EIA_Code: E96; SizeX_mm: 1.6; SizeY_mm: 0.8; SizeZ_mm: 1; Value2: 0.1W; SizeArea_mm2: 1.28; AEC Qualified: Y; VDC_V: 75V; AEC Category: Q200; AEC Grade: 0
R380 = CMP-0026658-1: RES, 10.0 k, 1%, 0.1 W, 0402; Manufacturer: Panasonic; Power_W: 100mW; TempCo: 100 ppm/C; Value_Code: 10k0; U/M: EA; Value: 10.0k; EIA_Code: E96; Res_ohm: 10k; SizeX_mm: 1; SizeY_mm: 0.5; SizeZ_mm: 0.6; Value2: 0.1W; VDC_V: 50V; AEC Category: Q200
SH-J2 = CMP-0003642-1: Shunt, 100mil, Flash Gold, Black; Manufacturer: Sullins Connector Solutions; Value: 1x2
U10 = CMP-0013512-3: Space Grade 40 MHz to 15 GHz Wideband Synthesizer with Phase Synchronization and JESD204B Support, HBD0064A (CFP-64); Manufacturer: Texas Instruments; CompType: IC; SizeZ_mm: 2.31; AEC Category: Q200; AEC Qualified: N
U11 = CMP-0074610-5: Radiation Hardness Assured (RHA) 6.5GHz Ultra Wideband Fully Differential Amplifier, FFK0014A (LCCC-14); Manufacturer: Texas Instruments; SizeZ_mm: 1.87; SizeX_mm: 6.0; SizeY_mm: 5.5; SizeArea_mm2: 33.0; CompType: IC; SizeAreaWB_mm2: 60.0; AEC Category: Q200; AEC Qualified: N; Rating: Space

## Sheet TIDA-010191-E2_Power-Supply_1.SchDoc: POWER SUPPLIES
size 558 x 431 mm; Date: Not shown in title block; ApprovedBy: Not shown in title block; CheckedBy: Not shown in title block; Author: Not shown in title block; CompanyName: Not shown in title block; DrawnBy: Avinash N; Engineer: Not shown in title block; Organization: Not shown in title block; Address1: Not shown in title block; Address2: Not shown in title block; Address3: Not shown in title block; Address4: Not shown in title block; DocumentNumber: 6; Revision: Use project parameter SCH_Rev; SheetNumber: 6; SheetTotal: 9; PageSetup: Record=PageOptions¦CenterHorizontal=True¦CenterVertical=True¦PrintScale=1.00¦XCorrection=1.00¦YCorrection=1.00¦PrintKind=0¦BorderSize=5000000¦LeftOffset=0¦BottomOffset=0¦Orientation=2¦PaperLength=1000¦PaperWidth=1000¦Scale=100¦PaperSource=15¦PrintQuality=600¦MediaType=1¦DitherType=10¦PaperKind=Letter¦PrintScaleMode=1
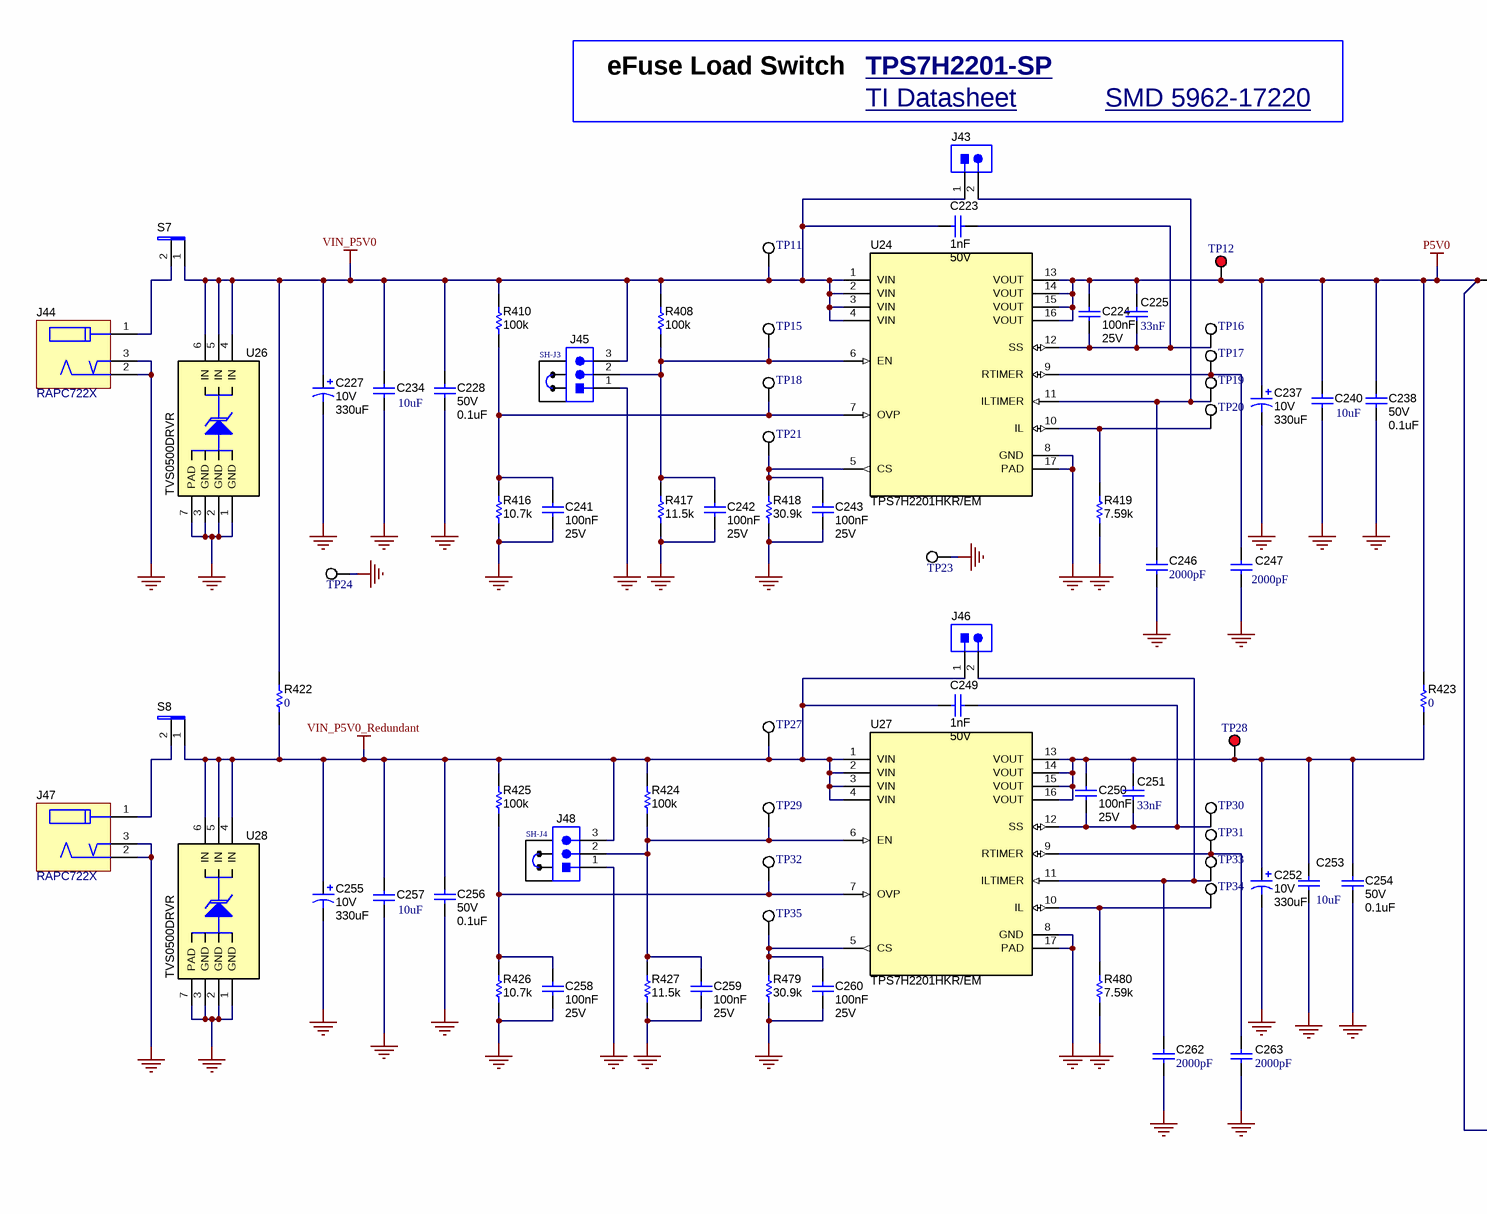
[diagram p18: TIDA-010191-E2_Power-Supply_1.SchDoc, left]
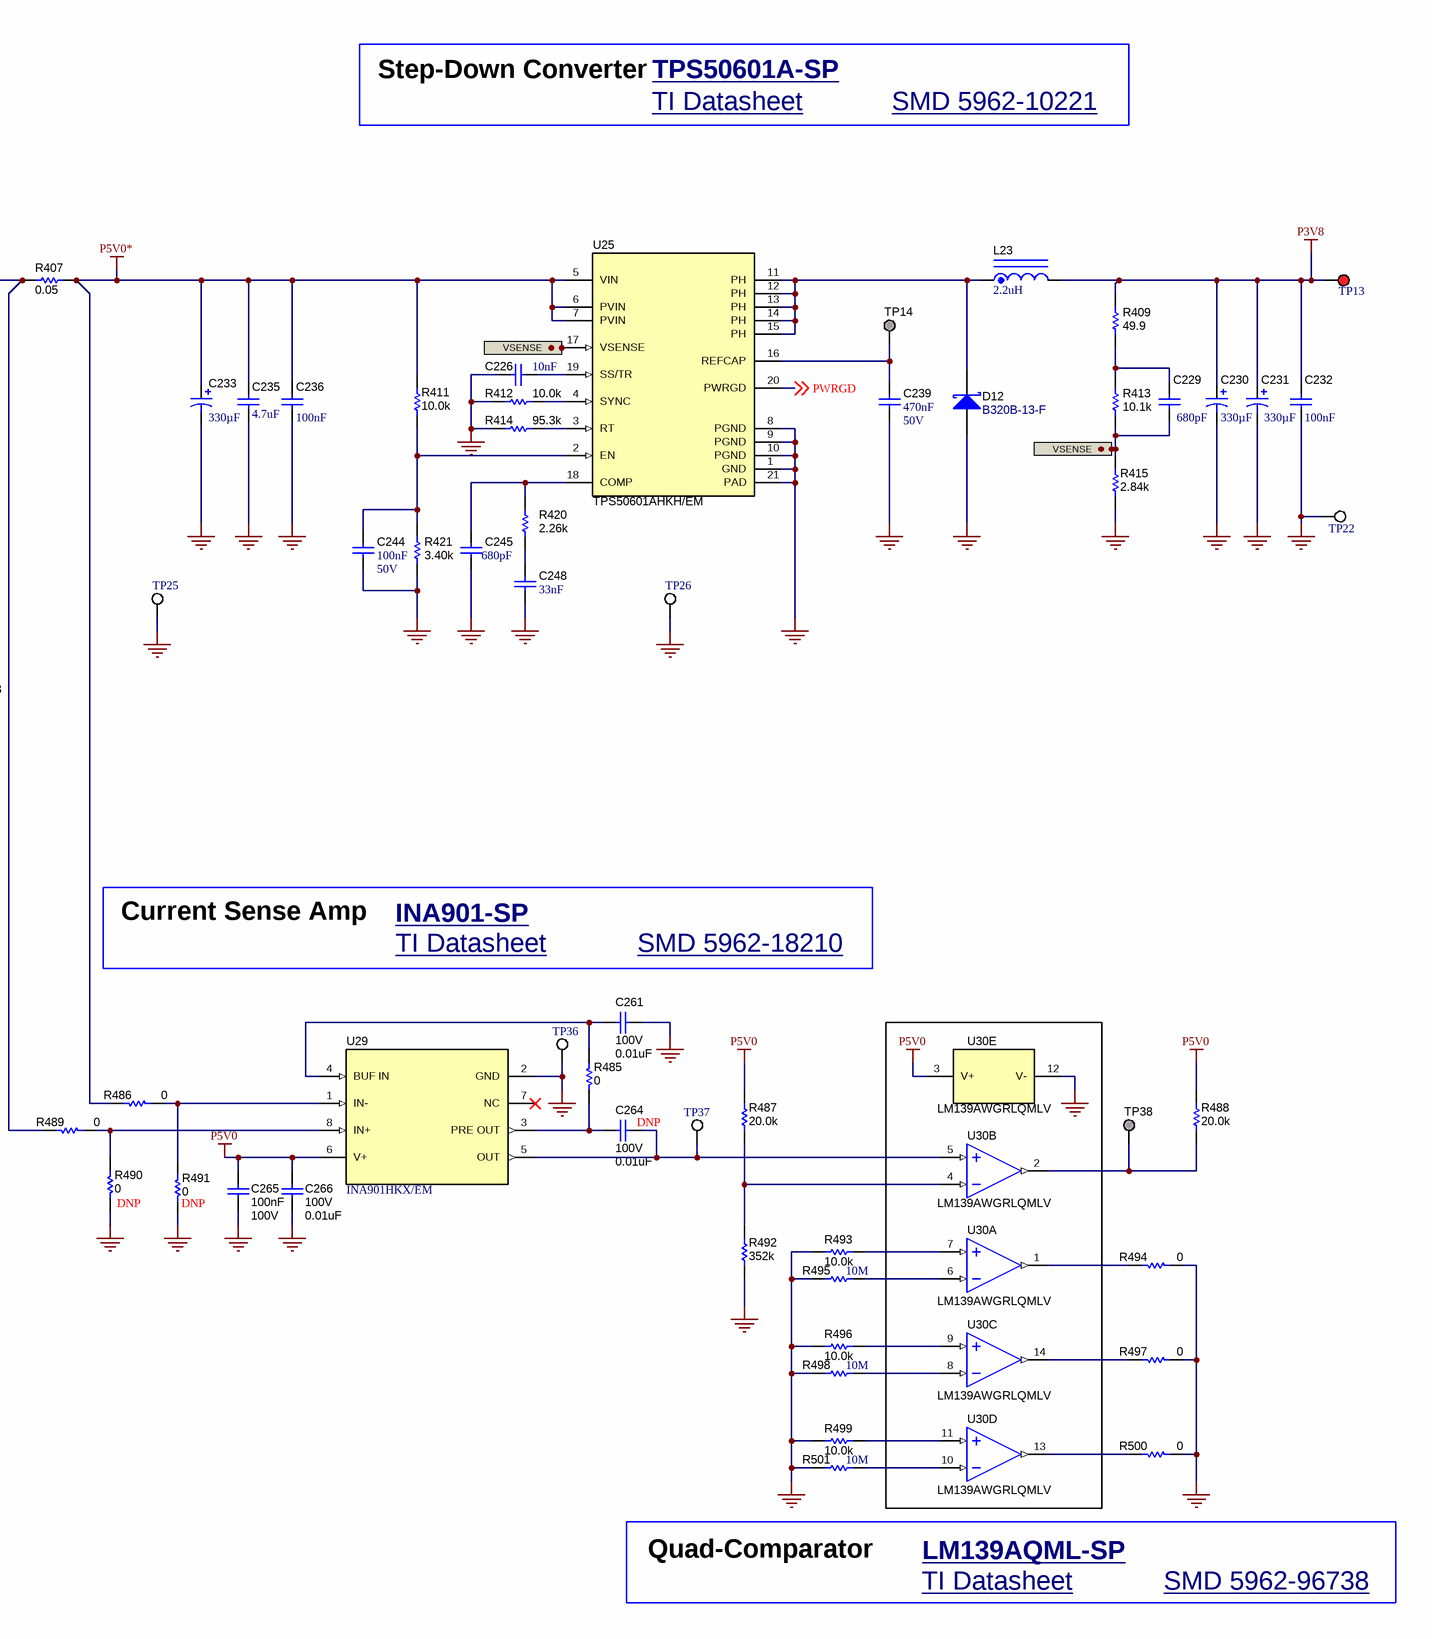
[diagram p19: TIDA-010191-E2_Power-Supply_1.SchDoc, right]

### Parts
C223  Cap_F: 1nF  VDC_V: 50V  [0805_HV]  (hidden comment: C0805C102J5RACTU)
C224  Cap_F: 100nF  VDC_V: 25V  [0805_HV]  (hidden comment: 08053C104JAZ2A)
C225  Cap_F: 33nF  [0805_HV]  (hidden comment: SR0805X7R333K1NT95(F)#M123A)
C226  Cap_F: 10nF  [0603]  (hidden comment: SR0603X7R103K1NT95(F)#M123A)
C227  VDC_V: 10V  ValueDisplayed: 330uF  [7343-43]  (hidden comment: T530X337M010ATE006)
C228  VDC_V: 50V  ValueDisplayed: 0.1uF  [1206]  (hidden comment: 12065C104JAT2A)
C229  Cap_F: 680pF  [0805_HV]  (hidden comment: SR0805X7R681K3NT95(F)#M123A)
C230  ValueDisplayed: 330µF  [7343-43]  (hidden comment: T541X337M010AH6720)
C231  ValueDisplayed: 330µF  [7343-43]  (hidden comment: T541X337M010AH6720)
C232  Cap_F: 100nF  [0805_HV]  (hidden comment: SR0805X7R104K1NT95(F)#M123A)
C233  ValueDisplayed: 330µF  [7343-43]  (hidden comment: T541X337M010AH6720)
C234  ValueDisplayed: 10uF  [2220_280]  (hidden comment: 22201C106MAT2A)
C235  ValueDisplayed: 4.7uF  [1210]  (hidden comment: C1210C475K8RACTU)
C236  Cap_F: 100nF  [0805_HV]  (hidden comment: 08055C104JAT2A)
C237  VDC_V: 10V  ValueDisplayed: 330uF  [7343-43]  (hidden comment: T530X337M010ATE006)
C238  VDC_V: 50V  ValueDisplayed: 0.1uF  [1206]  (hidden comment: 12065C104JAT2A)
C239  Cap_F: 470nF  VDC_V: 50V  [0805_HV]  (hidden comment: C2012X7R1H474K125AB)
C240  ValueDisplayed: 10uF  [2220_280]  (hidden comment: 22201C106MAT2A)
C241  Cap_F: 100nF  VDC_V: 25V  [0805_HV]  (hidden comment: 08053C104JAZ2A)
C242  Cap_F: 100nF  VDC_V: 25V  [0805_HV]  (hidden comment: 08053C104JAZ2A)
C243  Cap_F: 100nF  VDC_V: 25V  [0805_HV]  (hidden comment: 08053C104JAZ2A)
C244  Cap_F: 100nF  VDC_V: 50V  [0805_HV]  (hidden comment: 08055C104JAT2A)
C245  Cap_F: 680pF  [0805_HV]  (hidden comment: SR0805X7R681K3NT95(F)#M123A)
C246  ValueDisplayed: 2000pF  [1206]  (hidden comment: 12065A202JAT2A)
C247  ValueDisplayed: 2000pF  [1206]  (hidden comment: 12065A202JAT2A)
C248  Cap_F: 33nF  [0805_HV]  (hidden comment: SR0805X7R333K1NT95(F)#M123A)
C249  Cap_F: 1nF  VDC_V: 50V  [0805_HV]  (hidden comment: C0805C102J5RACTU)
C250  Cap_F: 100nF  VDC_V: 25V  [0805_HV]  (hidden comment: 08053C104JAZ2A)
C251  Cap_F: 33nF  [0805_HV]  (hidden comment: SR0805X7R333K1NT95(F)#M123A)
C252  VDC_V: 10V  ValueDisplayed: 330uF  [7343-43]  (hidden comment: T530X337M010ATE006)
C253  ValueDisplayed: 10uF  [2220_280]  (hidden comment: 22201C106MAT2A)
C254  VDC_V: 50V  ValueDisplayed: 0.1uF  [1206]  (hidden comment: 12065C104JAT2A)
C255  VDC_V: 10V  ValueDisplayed: 330uF  [7343-43]  (hidden comment: T530X337M010ATE006)
C256  VDC_V: 50V  ValueDisplayed: 0.1uF  [1206]  (hidden comment: 12065C104JAT2A)
C257  ValueDisplayed: 10uF  [2220_280]  (hidden comment: 22201C106MAT2A)
C258  Cap_F: 100nF  VDC_V: 25V  [0805_HV]  (hidden comment: 08053C104JAZ2A)
C259  Cap_F: 100nF  VDC_V: 25V  [0805_HV]  (hidden comment: 08053C104JAZ2A)
C260  Cap_F: 100nF  VDC_V: 25V  [0805_HV]  (hidden comment: 08053C104JAZ2A)
C261  VDC_V: 100V  ValueDisplayed: 0.01uF  [0805_HV]  (hidden comment: C0805C103F1GACTU)
C262  ValueDisplayed: 2000pF  [1206]  (hidden comment: 12065A202JAT2A)
C263  ValueDisplayed: 2000pF  [1206]  (hidden comment: 12065A202JAT2A)
C264  VDC_V: 100V  ValueDisplayed: 0.01uF  [0805_HV]  (hidden comment: C0805C103F1GACTU)
C265  Cap_F: 100nF  VDC_V: 100V  [0805_HV]  (hidden comment: C0805C104K1RACTU)
C266  VDC_V: 100V  ValueDisplayed: 0.01uF  [0805_HV]  (hidden comment: C0805C103F1GACTU)
D12  B320B-13-F  [SMB]
J43  HTSW-102-07-G-S  [Samtec_HTSW-102-07-G-S]  (value not drawn)
J44  RAPC722X  [CONN_RAPC722X]
J45  HTSW-103-07-G-S  [Samtec_HTSW-103-07-G-S]  (value not drawn)
J46  HTSW-102-07-G-S  [Samtec_HTSW-102-07-G-S]  (value not drawn)
J47  RAPC722X  [CONN_RAPC722X]
J48  HTSW-103-07-G-S  [Samtec_HTSW-103-07-G-S]  (value not drawn)
L23  ValueDisplayed: 2.2uH  [AE611PYA_1011]  (hidden comment: AE611PYA222MSZ)
R407  ValueDisplayed: 0.05  [4320]  (hidden comment: KRL11050-C-R050-F-T1)
R408  ValueDisplayed: 100k  [0805_HV]  (hidden comment: RT0805BRD07100KL)
R409  ValueDisplayed: 49.9  [0603]  (hidden comment: Resistor)
R410  ValueDisplayed: 100k  [0805_HV]  (hidden comment: RT0805BRD07100KL)
R411  ValueDisplayed: 10.0k  [0603]  (hidden comment: Resistor)
R412  ValueDisplayed: 10.0k  [0603]  (hidden comment: Resistor)
R413  ValueDisplayed: 10.1k  [0603]  (hidden comment: Resistor)
R414  ValueDisplayed: 95.3k  [0603]  (hidden comment: Resistor)
R415  ValueDisplayed: 2.84k  [0603]  (hidden comment: RT0603BRD072K84L)
R416  ValueDisplayed: 10.7k  [0603]  (hidden comment: CRCW060310K7FKEA)
R417  ValueDisplayed: 11.5k  [0603]  (hidden comment: CRCW060311K5FKEA)
R418  ValueDisplayed: 30.9k  [0603]  (hidden comment: CRCW060330K9FKEA)
R419  ValueDisplayed: 7.59k  [0603]  (hidden comment: RT0603BRD077K59L)
R420  ValueDisplayed: 2.26k  [0603]  (hidden comment: Resistor)
R421  ValueDisplayed: 3.40k  [0603]  (hidden comment: Resistor)
R422  ValueDisplayed: 0  [2512]  (hidden comment: RMC1JPTE)
R423  ValueDisplayed: 0  [2512]  (hidden comment: RMC1JPTE)
R424  ValueDisplayed: 100k  [0805_HV]  (hidden comment: RT0805BRD07100KL)
R425  ValueDisplayed: 100k  [0805_HV]  (hidden comment: RT0805BRD07100KL)
R426  ValueDisplayed: 10.7k  [0603]  (hidden comment: CRCW060310K7FKEA)
R427  ValueDisplayed: 11.5k  [0603]  (hidden comment: CRCW060311K5FKEA)
R479  ValueDisplayed: 30.9k  [0603]  (hidden comment: CRCW060330K9FKEA)
R480  ValueDisplayed: 7.59k  [0603]  (hidden comment: RT0603BRD077K59L)
R485  ValueDisplayed: 0  [0805]  (hidden comment: CRCW08050000Z0EA)
R486  ValueDisplayed: 0  [0805_HV]  (hidden comment: Resistor)
R487  ValueDisplayed: 20.0k  [0805_HV]  (hidden comment: Resistor)
R488  ValueDisplayed: 20.0k  [0805_HV]  (hidden comment: Resistor)
R489  ValueDisplayed: 0  [0805_HV]  (hidden comment: Resistor)
R490  ValueDisplayed: 0  [0805_HV]  (hidden comment: Resistor)
R491  ValueDisplayed: 0  [0805_HV]  (hidden comment: Resistor)
R492  ValueDisplayed: 352k  [0805_HV]  (hidden comment: RT0805BRD07352KL)
R493  ValueDisplayed: 10.0k  [0603]  (hidden comment: RT0603BRD0710KL)
R494  ValueDisplayed: 0  [0402]  (hidden comment: CMP-0026822-3)
R495  ValueDisplayed: 10M  [0603]  (hidden comment: CRCW060310M0DHEAP)
R496  ValueDisplayed: 10.0k  [0603]  (hidden comment: RT0603BRD0710KL)
R497  ValueDisplayed: 0  [0402]  (hidden comment: CMP-0026822-3)
R498  ValueDisplayed: 10M  [0603]  (hidden comment: CRCW060310M0DHEAP)
R499  ValueDisplayed: 10.0k  [0603]  (hidden comment: RT0603BRD0710KL)
R500  ValueDisplayed: 0  [0402]  (hidden comment: CMP-0026822-3)
R501  ValueDisplayed: 10M  [0603]  (hidden comment: CRCW060310M0DHEAP)
S7  CMP-0002125-2  [SW_ L101011MS02Q]  (value not drawn)
S8  CMP-0002125-2  [SW_ L101011MS02Q]  (value not drawn)
SH-J3  SPC02SYAN  [SPC02SYAN]  (value not drawn)
SH-J4  SPC02SYAN  [SPC02SYAN]  (value not drawn)
TP11  5002  [Keystone5002]  (value not drawn)
TP12  5000  [Keystone5000]  (value not drawn)
TP13  5000  [Keystone5000]  (value not drawn)
TP14  TP_SM_1MM  [TP_SM_1MM]  (value not drawn)  (no BOM)
TP15  5002  [Keystone5002]  (value not drawn)
TP16  5002  [Keystone5002]  (value not drawn)
TP17  5002  [Keystone5002]  (value not drawn)
TP18  5002  [Keystone5002]  (value not drawn)
TP19  5002  [Keystone5002]  (value not drawn)
TP20  5002  [Keystone5002]  (value not drawn)
TP21  5002  [Keystone5002]  (value not drawn)
TP22  5015  [Testpoint_Keystone_Miniature]  (value not drawn)
TP23  5015  [Testpoint_Keystone_Miniature]  (value not drawn)
TP24  5015  [Testpoint_Keystone_Miniature]  (value not drawn)
TP25  5015  [Testpoint_Keystone_Miniature]  (value not drawn)
TP26  5015  [Testpoint_Keystone_Miniature]  (value not drawn)
TP27  5002  [Keystone5002]  (value not drawn)
TP28  5000  [Keystone5000]  (value not drawn)
TP29  5002  [Keystone5002]  (value not drawn)
TP30  5002  [Keystone5002]  (value not drawn)
TP31  5002  [Keystone5002]  (value not drawn)
TP32  5002  [Keystone5002]  (value not drawn)
TP33  5002  [Keystone5002]  (value not drawn)
TP34  5002  [Keystone5002]  (value not drawn)
TP35  5002  [Keystone5002]  (value not drawn)
TP36  5015  [Testpoint_Keystone_Miniature]  (value not drawn)
TP37  5002  [Keystone5002]  (value not drawn)
TP38  TP_SM_1MM  [TP_SM_1MM]  (value not drawn)  (no BOM)
U24  TPS7H2201HKR/EM  [HKR0016A_Custom_A]
U25  TPS50601AHKH/EM  [HKH0020A_CUSTOM_A]
U26  TVS0500DRVR  [DRV0006A]
U27  TPS7H2201HKR/EM  [HKR0016A_Custom_A]
U28  TVS0500DRVR  [DRV0006A]
U29  INA901HKX/EM  [HKX0008A_Custom_A]
U30  LM139AWGRLQMLV  [NAC0014A_N]  (parts A,B,C,D,E of 5)

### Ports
VSENSE (in), VSENSE (out)

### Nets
GND: C226.1 C227.2(-) C228.1 C230.2(-) C231.2(-) C232.2 C233.2(-) C234.2 C235.2 C236.2 C237.2(-) C238.1 C239.2 C240.2 C241.2 C242.2 C243.2 C244.2 C245.2 C246.1 C247.1 C248.2 C252.2(-) C253.2 C254.1 C255.2(-) C256.1 C257.2 C258.2 C259.2 C260.2 C261.2 C262.1 C263.1 C265.2 C266.2 D12.2(A) J44.2 J44.3 J45.1 J47.2 J47.3 J48.1 R412.2 R414.2 R415.1 R416.1 R417.1 R418.1 R419.1 R421.1 R426.1 R427.1 R479.1 R480.1 R490.1 R491.1 R492.1 R493.1 R494.1 R495.1 R496.1 R497.1 R498.1 R499.1 R500.1 R501.1 TP22.1 TP23.1 TP24.1 TP25.1 TP26.1 TP36.1 U24.8(GND) U24.17(PAD) U25.1(GND) U25.8(PGND) U25.9(PGND) U25.10(PGND) U25.21(PAD) U26.1(GND) U26.2(GND) U26.3(GND) U26.7(PAD) U27.8(GND) U27.17(PAD) U28.1(GND) U28.2(GND) U28.3(GND) U28.7(PAD) U29.2(GND) U30.12(V-)
P3V8: C230.1(+) C231.1(+) C232.1 L23.2 R409.2 TP13.1
P5V0: C224.1 C225.1 C237.1(+) C238.2 C240.1 C265.1 C266.1 R407.1 R423.2 R487.1 R488.1 R489.1 TP12.1 U24.13(VOUT) U24.14(VOUT) U24.15(VOUT) U24.16(VOUT) U29.6(V+) U30.3(V+)
P5V0*: C233.1(+) C235.1 C236.1 R407.2 R411.2 R486.1 U25.5(VIN) U25.6(PVIN) U25.7(PVIN)
VIN_P5V0: C223.2 C227.1(+) C228.2 C234.1 J43.1 J45.3 R408.2 R410.2 R422.1 S7.1 TP11.1 U24.1(VIN) U24.2(VIN) U24.3(VIN) U24.4(VIN) U26.4(IN) U26.5(IN) U26.6(IN)
VIN_P5V0_Redundant: C249.2 C255.1(+) C256.2 C257.1 J46.1 J48.3 R422.2 R424.2 R425.2 S8.1 TP27.1 U27.1(VIN) U27.2(VIN) U27.3(VIN) U27.4(VIN) U28.4(IN) U28.5(IN) U28.6(IN)
PWRGD: U25.20(PWRGD) ; off-sheet PWRGD
VSENSE: C229.2 R413.1 R415.2 U25.17(VSENSE) ; port VSENSE
NetC223_1: C223.1 C224.2 C225.2 TP16.1 U24.12(SS)
NetC226_2: C226.2 U25.19(SS/TR)
NetC229_1: C229.1 R409.1 R413.2
NetC239_1: C239.1 TP14.1 U25.16(REFCAP)
NetC241_1: C241.1 R410.1 R416.2 TP18.1 U24.7(OVP)
NetC242_1: C242.1 J45.2 R408.1 R417.2 TP15.1 U24.6(EN)
NetC243_1: C243.1 R418.2 TP21.1 U24.5(CS)
NetC244_1: C244.1 R411.1 R421.2 U25.2(EN)
NetC245_1: C245.1 R420.2 U25.18(COMP)
NetC246_2: C246.2 J43.2 TP19.1 U24.11(ILTIMER)
NetC247_2: C247.2 TP17.1 U24.9(RTIMER)
NetC248_1: C248.1 R420.1
NetC249_1: C249.1 C250.2 C251.2 TP30.1 U27.12(SS)
NetC250_1: C250.1 C251.1 C252.1(+) C253.1 C254.2 R423.1 TP28.1 U27.13(VOUT) U27.14(VOUT) U27.15(VOUT) U27.16(VOUT)
NetC258_1: C258.1 R425.1 R426.2 TP32.1 U27.7(OVP)
NetC259_1: C259.1 J48.2 R424.1 R427.2 TP29.1 U27.6(EN)
NetC260_1: C260.1 R479.2 TP35.1 U27.5(CS)
NetC261_1: C261.1 R485.2 U29.4(BUF_IN)
NetC262_2: C262.2 J46.2 TP33.1 U27.11(ILTIMER)
NetC263_2: C263.2 TP31.1 U27.9(RTIMER)
NetC264_1: C264.1 R485.1 U29.3(PRE_OUT)
NetC264_2: C264.2 TP37.1 U29.5(OUT) U30.5(+IN1)
NetD12_1: D12.1(K) L23.1 U25.11(PH) U25.12(PH) U25.13(PH) U25.14(PH) U25.15(PH)
NetJ44_1: J44.1 S7.2
NetJ47_1: J47.1 S8.2
NetR412_1: R412.1 U25.4(SYNC)
NetR414_1: R414.1 U25.3(RT)
NetR419_2: R419.2 TP20.1 U24.10(IL)
NetR480_2: R480.2 TP34.1 U27.10(IL)
NetR486_2: R486.2 R491.2 U29.1(IN-)
NetR487_2: R487.2 R492.2 U30.4(-IN1)
NetR488_2: R488.2 TP38.1 U30.2(OUT1)
NetR489_2: R489.2 R490.2 U29.8(IN+)
NetR493_2: R493.2 U30.7(+IN2)
NetR494_2: R494.2 U30.1(OUT2)
NetR495_2: R495.2 U30.6(-IN2)
NetR496_2: R496.2 U30.9(+IN3)
NetR497_2: R497.2 U30.14(OUT3)
NetR498_2: R498.2 U30.8(-IN3)
NetR499_2: R499.2 U30.11(+IN4)
NetR500_2: R500.2 U30.13(OUT4)
NetR501_2: R501.2 U30.10(-IN4)

Not connected (* = marked no-connect by the designer): U29 7(NC)*

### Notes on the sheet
- eFuse Load Switch
- TPS7H2201-SP <http://www.ti.com/product/TPS7H2201-SP>
- Step-Down Converter
- TPS50601A-SP <http://www.ti.com/product/TPS50601A-SP>
- TI Datasheet <http://www.ti.com/lit/gpn/tps7h2201-sp>
- SMD 5962-17220 <https://landandmaritimeapps.dla.mil/Downloads/MilSpec/Smd/17220.pdf>
- TI Datasheet <http://www.ti.com/lit/gpn/tps50601a-sp>
- SMD 5962-10221 <https://landandmaritimeapps.dla.mil/Downloads/MilSpec/Smd/10221.pdf>
- Current Sense Amp
- INA901-SP <http://www.ti.com/product/INA901-SP>
- TI Datasheet <http://www.ti.com/lit/gpn/INA901-SP>
- SMD 5962-18210 <https://landandmaritimeapps.dla.mil/Downloads/MilSpec/Smd/18210.pdf>
- (near C264) DNP
- (near R490) DNP
- (near R491) DNP
- Quad-Comparator
- LM139AQML-SP <http://www.ti.com/product/LM139AQML-SP>
- TI Datasheet <http://www.ti.com/lit/gpn/lm139aqml-sp>
- SMD 5962-96738 <https://landandmaritimeapps.dla.mil/Downloads/MilSpec/Smd/96738.pdf>

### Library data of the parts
C223 C249 = CMP-0007711-2: CAP, CERM, 1000 pF, 50 V, +/- 5%, X7R, 0805; Manufacturer: Kemet; TaMin_C: -55°C; ESR_ohm: 0.384; Polarized: N; SizeAreaWB_mm2: 6.75; Value1: 0.384 ohm; U/M: EA; Value: 1000pF; TaMax_C: 125°C; SizeZ_mm: 1.45; SizeX_mm: 2; SizeY_mm: 1.25; Cap_Case: 0805; SizeArea_mm2: 2.5; IRMS_A: 214mA; AEC Category: Q200
C224 C241-C243 C250 C258-C260 = CMP-0007566-2: CAP, CERM, 0.1 uF, 25 V, +/- 5%, X7R, 0805; Manufacturer: AVX; TaMin_C: -55°C; Polarized: N; SizeAreaWB_mm2: 6.75; Value1: Unknown; U/M: EA; Value: 0.1uF; TaMax_C: 125°C; SizeZ_mm: 1.45; SizeX_mm: 2; SizeY_mm: 1.25; Cap_Case: 0805; SizeArea_mm2: 2.5; AEC Category: Q200
C225 C248 C251 = CMP-0079724-1: CAP, CERM, 0.033 µF, 25 V,+/- 10%, X7R, 0805; Manufacturer: Presidio Components; TaMin_C: -55°C; Polarized: N; SizeAreaWB_mm2: 6.75; U/M: EA; Value: 0.033uF; TaMax_C: 125°C; SizeZ_mm: 1.45; SizeX_mm: 2; SizeY_mm: 1.25; Cap_Case: 0805; Value2: 25V; SizeArea_mm2: 2.5; AEC Category: Q200
C226 = CMP-0079721-1: CAP, CERM, 0.01 µF, 25 V,+/- 10%, X7R, 0603; Manufacturer: Presidio Components; TaMin_C: -55°C; Polarized: N; SizeAreaWB_mm2: 4.68; U/M: EA; Value: 0.01uF; TaMax_C: 125°C; SizeZ_mm: 1; SizeX_mm: 1.6; SizeY_mm: 0.8; Value2: 25V; SizeArea_mm2: 1.28; AEC Category: Q200; ValueDisplayed: 0.01µF
C227 C237 C252 C255 = CMP-0012657-3: CAP, Tantalum Polymer, 330 uF, 10 V, +/- 20%, 0.006 ohm, 7343-43 SMD; Manufacturer: Kemet; TaMin_C: -55°C; ESR_ohm: 6m; Polarized: Y; SizeAreaWB_mm2: 58.59; Value: 330uF; TaMax_C: 125°C; SizeZ_mm: 4.3; SizeX_mm: 7.3; SizeArea_mm2: 31.39; CompType: Capacitor; AEC Qualified: N; Cap_F: 330µF; IRMS_A: 6.7A; AEC Category: Q200
C228 C238 C254 C256 = CMP-0008532-2: CAP, CERM, 0.1 uF, 50 V, +/- 5%, X7R, 1206; Manufacturer: AVX; TaMin_C: -55°C; ESR_ohm: 0.037; Polarized: N; SizeAreaWB_mm2: 10.92; Value1: 0.037 ohm; U/M: EA; Value: 0.1uF; TaMax_C: 125°C; SizeZ_mm: 1.35; SizeX_mm: 3.2; SizeY_mm: 1.6; SizeArea_mm2: 5.12; Cap_F: 100nF; AEC Category: Q200
C229 C245 = CMP-0079725-1: CAP, CERM, 680 pF, 10 V,+/- 10%, X7R, 0805; Manufacturer: Presidio Components; TaMin_C: -55°C; Polarized: N; SizeAreaWB_mm2: 6.75; U/M: EA; Value: 680pF; TaMax_C: 125°C; SizeZ_mm: 1.45; SizeX_mm: 2; SizeY_mm: 1.25; Cap_Case: 0805; Value2: 10V; SizeArea_mm2: 2.5; AEC Category: Q200
C230 C231 C233 = CMP-0079639-1: CAP, Tantalum Polymer, 330 µF, 10 V,+/- 20%, 7343-43 SMD; Manufacturer: Kemet; IRMS_A: 6.708A; SizeAreaWB_mm2: 58.59; SizeArea_mm2: 31.39; AEC Qualified: N; AEC Category: Q200; Value: 330uF; TaMax_C: 125°C; SizeZ_mm: 4.3; Polarized: Y; TaMin_C: -55°C; VDC_V: 10V; CompType: Capacitor; SizeX_mm: 7.3
C232 = CMP-0079722-1: CAP, CERM, 0.1 µF, 25 V,+/- 10%, X7R, 0805; Manufacturer: Presidio Components; TaMin_C: -55°C; Polarized: N; SizeAreaWB_mm2: 6.75; U/M: EA; Value: 0.1uF; TaMax_C: 125°C; SizeZ_mm: 1.45; SizeX_mm: 2; SizeY_mm: 1.25; Cap_Case: 0805; Value2: 25V; SizeArea_mm2: 2.5; AEC Category: Q200; ValueDisplayed: 0.1µF
C234 C240 C253 C257 = CMP-0009304-2: CAP, CERM, 10 uF, 100 V, +/- 20%, X7R, 2220; Manufacturer: AVX; TaMin_C: -55°C; Polarized: N; SizeAreaWB_mm2: 53.9; Value1: Unknown; U/M: EA; Value: 10uF; TaMax_C: 125°C; SizeZ_mm: 2.8; SizeX_mm: 5.7; SizeY_mm: 5; Cap_Case: 2220; Value2: 100V; SizeArea_mm2: 28.5; Cap_F: 10µF; AEC Category: Q200
C235 = CMP-0009088-1: CAP, CERM, 4.7 uF, 10 V, +/- 10%, X7R, 1210; Manufacturer: Kemet; TaMin_C: -55°C; Polarized: N; SizeAreaWB_mm2: 14.7; Value1: Unknown; U/M: EA; Value: 4.7uF; TaMax_C: 125°C; SizeZ_mm: 1.35; SizeX_mm: 3.2; SizeY_mm: 2.5; Value2: 10V; SizeArea_mm2: 8; Cap_F: 4.7µF; AEC Category: Q200
C236 = CMP-0007631-2: CAP, CERM, 0.1 uF, 50 V, +/- 5%, X7R, 0805; Manufacturer: AVX; TaMin_C: -55°C; ESR_ohm: 0.024; Polarized: N; SizeAreaWB_mm2: 6.75; Value1: 0.024 ohm; U/M: EA; Value: 0.1uF; TaMax_C: 125°C; SizeZ_mm: 1.45; SizeX_mm: 2; SizeY_mm: 1.25; Cap_Case: 0805; Value2: 50V; SizeArea_mm2: 2.5; AEC Category: Q200
C239 = CMP-0007880-2: CAP, CERM, 0.47 uF, 50 V, +/- 10%, X7R, 0805; Manufacturer: TDK; TaMin_C: -55°C; ESR_ohm: 0.022012; Polarized: N; SizeAreaWB_mm2: 6.75; Value1: 0.022012 ohm; U/M: EA; Value: 0.47uF; TaMax_C: 125°C; SizeZ_mm: 1.45; SizeX_mm: 2; SizeY_mm: 1.25; Cap_Case: 0805; SizeArea_mm2: 2.5; IRMS_A: 1.39566A; AEC Category: Q200
C244 = CMP-0007631-2: CAP, CERM, 0.1 uF, 50 V, +/- 5%, X7R, 0805; Manufacturer: AVX; TaMin_C: -55°C; ESR_ohm: 0.024; Polarized: N; SizeAreaWB_mm2: 6.75; Value1: 0.024 ohm; U/M: EA; Value: 0.1uF; TaMax_C: 125°C; SizeZ_mm: 1.45; SizeX_mm: 2; SizeY_mm: 1.25; Cap_Case: 0805; SizeArea_mm2: 2.5; AEC Category: Q200
C246 C247 C262 C263 = CMP-0082630-1: CAP, CERM, 2000 pF, 50 V,+/- 5%, C0G/NP0, 1206; Manufacturer: AVX; Cap_F: 2nF; SizeAreaWB_mm2: 10.92; SizeArea_mm2: 5.12; AEC Qualified: N; AEC Category: Q200; Value: 2000pF; TaMax_C: 125°C; SizeZ_mm: 1.35; Green_REACh: Incomplete; TaMin_C: -55°C; VDC_V: 50V; SizeY_mm: 1.6; Green_Lifecycle: Active; U/M: EA; SizeX_mm: 3.2
C261 C264 C266 = CMP-0007716-2: CAP, CERM, 0.01 uF, 100 V, +/- 1%, C0G/NP0, 0805; Manufacturer: Kemet; TaMin_C: -55°C; Polarized: N; SizeAreaWB_mm2: 6.75; Value1: Unknown; U/M: EA; Value: 0.01uF; TaMax_C: 125°C; SizeZ_mm: 1.45; SizeX_mm: 2; SizeY_mm: 1.25; Cap_Case: 0805; SizeArea_mm2: 2.5; Cap_F: 10nF; AEC Category: Q200
C265 = CMP-0007722-2: CAP, CERM, 0.1 uF, 100 V, +/- 10%, X7R, 0805; Manufacturer: Kemet; TaMin_C: -55°C; ESR_ohm: 0.064; Polarized: N; SizeAreaWB_mm2: 6.75; Value1: 0.064 ohm; U/M: EA; Value: 0.1uF; TaMax_C: 125°C; SizeZ_mm: 1.45; SizeX_mm: 2; SizeY_mm: 1.25; Cap_Case: 0805; SizeArea_mm2: 2.5; IRMS_A: 1.64A; AEC Category: Q200
D12 = CMP-0028348-2: Diode, Schottky, 20 V, 3 A, SMB; Manufacturer: Diodes Inc.; Io_A: 3A; Green_Lifecycle: Not Set; SizeAreaWB_mm2: 44.156; Vr_V: 20V; Green_REACh: Incomplete; TJmax_C: 125°C; Value: 20V; SizeZ_mm: 2.6; SizeX_mm: 5.6; SizeY_mm: 3.81; Vf_V: 500mV; Value2: 0.5V; SizeArea_mm2: 21.336; AEC Category: Q101; RJC_CperW: 25
J43 J46 = CMP-0075483-1: as J40 on sheet TIDA-010191-E2_LMX2615_LO
J44 J47 = CMP-0074940-1: Power Jack, mini, 2.1mm OD, R/A, TH; Manufacturer: Switchcraft; CNHeader: False; Green_Lifecycle: Not Set; Green_REACh: Incomplete
J45 J48 = CMP-0075484-1: Header, 100mil, 3x1, Gold, TH; Manufacturer: Samtec; Green_REACh: Passed; CT: False; Green_Lifecycle: Active; CNHeader: True
L23 = CMP-0061180-1: Inductor, Composite, 2.2 uH, 18.4 A, 0.0028 ohm, SMD; Manufacturer: Coilcraft CPS; Isat: 34A @ 30% inductance drop; Irms: 18.4A @ 20C rise; Green_Lifecycle: Not Set; SizeAreaWB_mm2: 159.6; DCR_ohm: 2.8m; Green_REACh: Incomplete; Value: 2.2uH; Imax_A: 18.4A; SizeZ_mm: 10; SizeY_mm: 11.3; SizeArea_mm2: 113; Ind_H: 2.2µH; AEC Qualified: N; AEC Category: Q200
R407 = CMP-0015099-2: RES, 0.05, 1%, 6 W, 4320_WIDE; Manufacturer: Susumu Co Ltd; Power_W: 6W; TempCo: 50 ppm/C; Value_Code: R050; U/M: EA; Value: 0.05; EIA_Code: E96; AEC Category: Q200
R408 R410 R424 R425 = CMP-0019441-2: RES, 100 k, 0.1%, 0.125 W, 0805; Manufacturer: Yageo America; Power_W: 125mW; TempCo: 25 ppm/C; U/M: EA; Value: 100k; EIA_Code: E192; SizeX_mm: 2; SizeY_mm: 1.25; SizeZ_mm: 1.45; Value2: 0.125W; SizeArea_mm2: 2.5; VDC_V: 150V; AEC Category: Q200
R409 = CMP-0022707-2: RES, 49.9, 1%, 0.1 W, AEC-Q200 Grade 0, 0603; PartNumber: ERJ-3EKF49R9V; Manufacturer: Panasonic; Value: 49.9; Value_Code: 49R9; Power_W: 100mW; Value2: 0.1W; TempCo: 100 ppm/C; SizeArea_mm2: 1.28; SizeX_mm: 1.6; SizeY_mm: 0.8; SizeZ_mm: 1; EIA_Code: E96; U/M: EA; AEC Category: Q200; AEC Qualified: Y; AEC Grade: 0
R411 R412 = CMP-0022684-3: RES, 10.0 k, 1%, 0.1 W, 0603; PartNumber: ERJ-3EKF1002V; Manufacturer: Panasonic; Value: 10.0k; Res_ohm: 10k; Value_Code: 10k0; Power_W: 100mW; Value2: 0.1W; VDC_V: 75V; TempCo: 100 ppm/C; SizeArea_mm2: 1.28; SizeX_mm: 1.6; SizeY_mm: 0.8; SizeZ_mm: 1; EIA_Code: E96; U/M: EA; AEC Category: Q200
R413 = CMP-0023646-2: RES, 10.1 k, 0.1%, 0.1 W, 0603; PartNumber: RT0603BRD0710K1L; Manufacturer: Yageo America; Value: 10.1k; Value_Code: 10k1; Power_W: 100mW; Value2: 0.1W; VDC_V: 75V; TempCo: 25 ppm/C; SizeArea_mm2: 1.28; SizeX_mm: 1.6; SizeY_mm: 0.8; SizeZ_mm: 1; EIA_Code: E192; U/M: EA; AEC Category: Q200
R414 = CMP-0022659-4: RES, 95.3 k, 1%, 0.1 W, AEC-Q200 Grade 0, 0603; PartNumber: CRCW060395K3FKEA; Manufacturer: Vishay-Dale; Value: 95.3k; Value_Code: 95k3; Power_W: 100mW; Value2: 0.1W; VDC_V: 75V; TempCo: 100 ppm/C; SizeArea_mm2: 1.28; SizeX_mm: 1.6; SizeY_mm: 0.8; SizeZ_mm: 1; EIA_Code: E96; AEC Category: Q200; AEC Qualified: Y; AEC Grade: 0
R415 = CMP-0024083-3: RES, 2.84 k, 0.1%, 0.1 W, 0603; Manufacturer: Yageo America; Power_W: 100mW; TempCo: 25 ppm/C; Value_Code: 2k84; U/M: EA; Value: 2.84k; EIA_Code: E192; SizeX_mm: 1.6; SizeY_mm: 0.8; SizeZ_mm: 1; Value2: 0.1W; SizeArea_mm2: 1.28; VDC_V: 75V; AEC Category: Q200
R416 R426 = CMP-0022001-4: RES, 10.7 k, 1%, 0.1 W, AEC-Q200 Grade 0, 0603; Manufacturer: Vishay-Dale; Power_W: 100mW; TempCo: 100 ppm/C; Value_Code: 10k7; Value: 10.7k; EIA_Code: E96; SizeX_mm: 1.6; SizeY_mm: 0.8; SizeZ_mm: 1; Value2: 0.1W; SizeArea_mm2: 1.28; AEC Qualified: Y; VDC_V: 75V; AEC Category: Q200; AEC Grade: 0
R417 R427 = CMP-0022018-4: RES, 11.5 k, 1%, 0.1 W, AEC-Q200 Grade 0, 0603; Manufacturer: Vishay-Dale; Power_W: 100mW; TempCo: 100 ppm/C; Value_Code: 11k5; Value: 11.5k; EIA_Code: E96; SizeX_mm: 1.6; SizeY_mm: 0.8; SizeZ_mm: 1; Value2: 0.1W; SizeArea_mm2: 1.28; AEC Qualified: Y; VDC_V: 75V; AEC Category: Q200; AEC Grade: 0
R418 R479 = CMP-0022325-4: RES, 30.9 k, 1%, 0.1 W, AEC-Q200 Grade 0, 0603; Manufacturer: Vishay-Dale; Power_W: 100mW; TempCo: 100 ppm/C; Value_Code: 30k9; Value: 30.9k; EIA_Code: E96; SizeX_mm: 1.6; SizeY_mm: 0.8; SizeZ_mm: 1; Value2: 0.1W; SizeArea_mm2: 1.28; AEC Qualified: Y; VDC_V: 75V; AEC Category: Q200; AEC Grade: 0
R419 R480 = CMP-0024481-2: RES, 7.59 k, 0.1%, 0.1 W, 0603; Manufacturer: Yageo America; Power_W: 100mW; TempCo: 25 ppm/C; Value_Code: 7k59; U/M: EA; Value: 7.59k; EIA_Code: E192; SizeX_mm: 1.6; SizeY_mm: 0.8; SizeZ_mm: 1; Value2: 0.1W; SizeArea_mm2: 1.28; VDC_V: 75V; AEC Category: Q200
R420 = CMP-0022985-5: RES, 2.26 k, 1%, 0.1 W, 0603; PartNumber: RC0603FR-072K26L; Manufacturer: Yageo; Value: 2.26k; Value_Code: 2k26; Power_W: 100mW; Value2: 0.1W; VDC_V: 75V; TempCo: 100 ppm/C; SizeArea_mm2: 1.28; SizeX_mm: 1.6; SizeY_mm: 0.8; SizeZ_mm: 1; EIA_Code: E96; AEC Category: Q200; AEC Qualified: N; SizeAreaWB_mm2: 4.68
R421 = CMP-0022376-4: RES, 3.40 k, 1%, 0.1 W, AEC-Q200 Grade 0, 0603; PartNumber: CRCW06033K40FKEA; Manufacturer: Vishay-Dale; Value: 3.40k; Res_ohm: 3.4k; Value_Code: 3k40; Power_W: 100mW; Value2: 0.1W; VDC_V: 75V; TempCo: 100 ppm/C; SizeArea_mm2: 1.28; SizeX_mm: 1.6; SizeY_mm: 0.8; SizeZ_mm: 1; EIA_Code: E96; AEC Category: Q200; AEC Qualified: Y; AEC Grade: 0
R422 R423 = CMP-0080698-1: RES, 0, 0%, 1 W, AEC-Q200 Grade 0, 2512; Manufacturer: Kamaya; SizeAreaWB_mm2: 43.16; SizeArea_mm2: 20.16; AEC Qualified: Y; AEC Category: Q200; Value: 0; SizeZ_mm: 0.71; SizeY_mm: 3.2; Power_W: 1W; SizeX_mm: 6.3
R485 = CMP-0020442-3: RES, 0, 5%, 0.125 W, AEC-Q200 Grade 0, 0805; Manufacturer: Vishay-Dale; Value: 0; Value_Code: 0000; Power_W: 125mW; Value2: 0.125W; VDC_V: 150V; TempCo: 200 ppm/C; SizeArea_mm2: 2.5; SizeX_mm: 2; SizeY_mm: 1.25; SizeZ_mm: 1.45; EIA_Code: E24; AEC Category: Q200; AEC Qualified: Y
R486 R489-R491 = CMP-0020442-3: RES, 0, 5%, 0.125 W, AEC-Q200 Grade 0, 0805; PartNumber: CRCW08050000Z0EA; Manufacturer: Vishay-Dale; Value: 0; Value_Code: 0000; Power_W: 125mW; Value2: 0.125W; VDC_V: 150V; TempCo: 200 ppm/C; SizeArea_mm2: 2.5; SizeX_mm: 2; SizeY_mm: 1.25; SizeZ_mm: 1.45; EIA_Code: E24; AEC Category: Q200; AEC Qualified: Y
R487 R488 = CMP-0021614-3: RES, 20.0 k, 1%, 0.125 W, AEC-Q200 Grade 0, 0805; PartNumber: ERJ-6ENF2002V; Manufacturer: Panasonic; Value: 20.0k; Res_ohm: 20k; Value_Code: 20k0; Power_W: 125mW; Value2: 0.125W; TempCo: 100 ppm/C; SizeArea_mm2: 2.5; SizeX_mm: 2; SizeY_mm: 1.25; SizeZ_mm: 1.45; EIA_Code: E96; AEC Category: Q200; AEC Qualified: Y; AEC Grade: 0; SizeAreaWB_mm2: 6.75
R492 = CMP-0019984-1: RES, 352 k, 0.1%, 0.125 W, 0805; Manufacturer: Yageo America; Power_W: 125mW; TempCo: 25 ppm/C; U/M: EA; Value: 352k; EIA_Code: E192; SizeX_mm: 2; SizeY_mm: 1.25; SizeZ_mm: 1.45; Value2: 0.125W; SizeArea_mm2: 2.5; VDC_V: 150V; AEC Category: Q200
R493 R496 R499 = CMP-0023653-3: RES, 10.0 k, 0.1%, 0.1 W, 0603; Manufacturer: Yageo America; Power_W: 100mW; TempCo: 25 ppm/C; Value_Code: 10k0; U/M: EA; Value: 10.0k; EIA_Code: E192; Res_ohm: 10k; SizeX_mm: 1.6; SizeY_mm: 0.8; SizeZ_mm: 1; Value2: 0.1W; SizeArea_mm2: 1.28; VDC_V: 75V; AEC Category: Q200
R494 R497 R500 = CMP-0026822-3: as R223 on sheet TIDA-010191-E2_LMX2615_LO
R495 R498 R501 = CMP-0023358-4: RES, 10 M, 0.5%, 0.1 W, AEC-Q200 Grade 0, 0603; Manufacturer: Vishay-Dale; Power_W: 100mW; TempCo: 50 ppm/C; Value_Code: 10M0; Value: 10Meg; EIA_Code: E24; SizeX_mm: 1.6; SizeY_mm: 0.8; SizeZ_mm: 1; Value2: 0.1W; SizeArea_mm2: 1.28; AEC Qualified: Y; VDC_V: 75V; AEC Grade: 0; AEC Category: Q200
S7 S8 = CMP-0002125-2: SWITCH SLIDE SPST 4A PCB, TH; PartNumber: L101011MS02Q; Manufacturer: C&K Components; VDC_V: 125V; SwitchFunction: Off-On; PositionCount: 1; CurrentRating_mA: 4kA
SH-J3 SH-J4 = CMP-0003642-1: as SH-J2 on sheet TIDA-010191-E2_LMX2615_LO
TP11 TP15-TP21 TP27 TP29-TP35 TP37 = CMP-0055139-2: Test Point, Miniature, White, TH; Manufacturer: Keystone Electronics; ContactFinish: Silver; Green_Lifecycle: Active; Green_REACh: Passed; CNHeader: FALSE; CT: TRUE
TP12 TP13 TP28 = CMP-0055137-2: Test Point, Miniature, Red, TH; Manufacturer: Keystone Electronics; CNHeader: FALSE; Green_Lifecycle: Active; Green_REACh: Passed; ContactFinish: Silver; CT: TRUE
TP14 TP38 = CMP-0003825-1: 1mm Test Point, SMT; Manufacturer: Any
TP22-TP26 TP36 = CMP-0055152-2: Test Point, Miniature, SMT; Manufacturer: Keystone Electronics; CNHeader: FALSE; Green_Lifecycle: Active; Green_REACh: Passed; CT: TRUE
U24 U27 = CMP-0078485-2: Radiation Hardened 7-V, 6-A Load Switch, HKR0016A (CFP-16); Manufacturer: Texas Instruments; SizeZ_mm: 2.33; SizeX_mm: 25.142; SizeY_mm: 11.26; AEC Category: Q200; AEC Qualified: N; SizeArea_mm2: 283.09892; CompType: IC; SizeAreaWB_mm2: 359.90292; Rating: Space
U25 = CMP-0077088-1: Radiation Hardened 3.0- to 6.3-V Input, 6-A Synchronous Buck Converter, HKH0020A (CFP-20); Alternate Manufacturer: Texas Instruments; CompType: IC; SizeZ_mm: 2.54; U/M: EA
U26 U28 = CMP-0077837-1: 5-V Precision Surge Protection Clamp, DRV0006A (WSON-6); Alternate Manufacturer: Texas Instruments; SizeAreaWB_mm2: 9.0; SizeZ_mm: 0.8; SizeX_mm: 2.0; SizeArea_mm2: 4.0; CompType: IC; AEC Qualified: N; AEC Category: Q200
U29 = CMP-0081563-2: Voltage Output, Unidirectional Measurement Current-Shunt Monitor, HKX0008A (CFP-8); Manufacturer: Texas Instruments; SizeZ_mm: 2.8; Rating: Space; AEC Category: Q200; CompType: IC; AEC Qualified: N
U30 = CMP-0068426-2: Low Power Low Offset Voltage Quad Comparator, NAC0014A (CFP-14); Manufacturer: Texas Instruments; AEC Qualified: N; SizeX_mm: 10.41; SizeArea_mm2: 103.16; SizeZ_mm: 2.03; Rating: Space; CompType: Amplifiers; AEC Category: Q200; SizeAreaWB_mm2: 147.8; SizeY_mm: 9.91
